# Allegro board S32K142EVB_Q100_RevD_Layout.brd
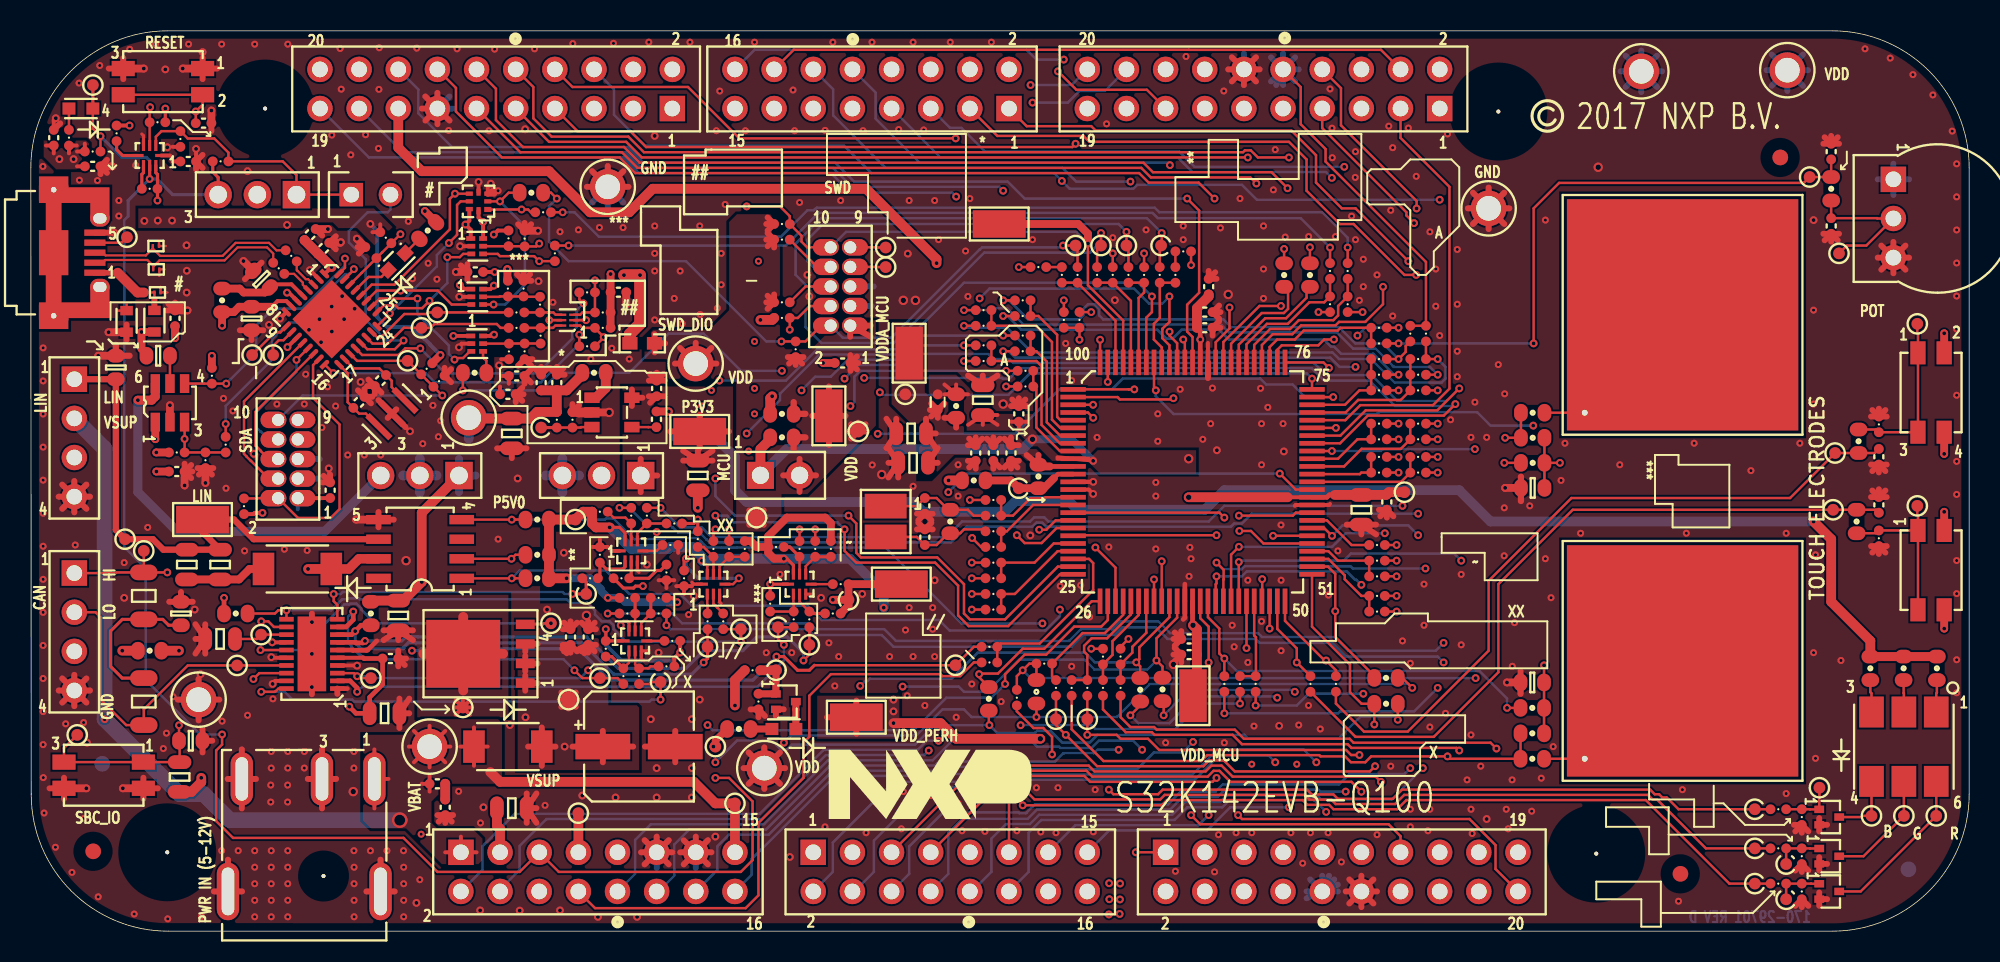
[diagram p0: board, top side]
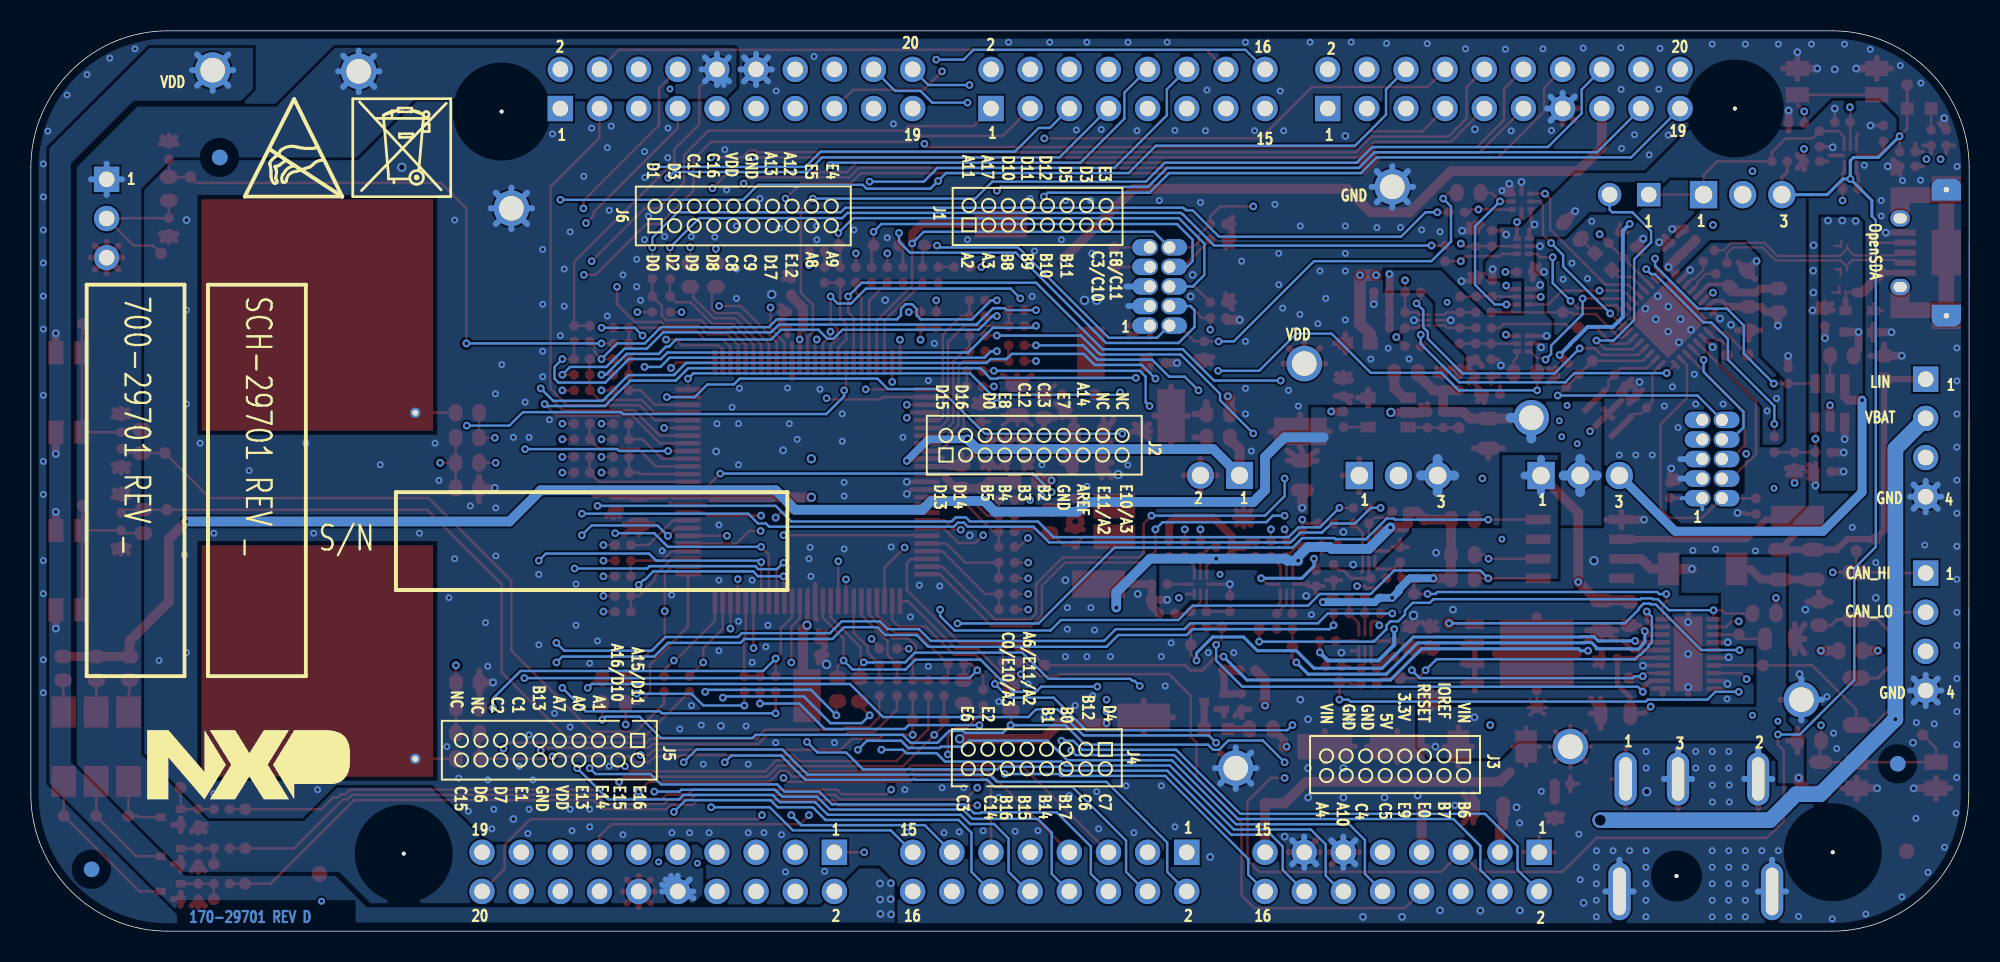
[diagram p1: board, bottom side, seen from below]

Outline 125.76 x 58.42 mm; copper layers: TOP, L2_GND, L3_MIX, BOTTOM. Coordinates in mm from the lower left corner of the outline.
Outline path: 0,49.53 0.03,8.89 0.03,8.89 arc(2.63,2.6) 8.92,0 116.87,0 arc(123.15,2.6) 125.76,8.89 125.76,49.53 arc(123.15,55.82) 116.87,58.42 8.89,58.42 arc(2.6,55.82) 0,49.53

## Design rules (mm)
net group CLOCK: nets SDA_EXTAL SDA_XTAL
net group SDA_USB_CONN_D: nets SDA_USB_CONN_DN SDA_USB_CONN_DP
net group USB_SI_CONN_D: nets SDA_USB_DN SDA_USB_DP
net group POW: nets MIC2005_CSLEW P5V_SDA POWER_EN SDA_RST SDA_USB_P5V_SENSE VTRG_EN
net group POWER_SPACE: nets P5V0_SDA_USB_CONN_VBUS P5V_SDA_PSW SDA_VOUT33
nets with their own width: min track width 0.254; nets GND

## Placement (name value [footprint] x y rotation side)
C1  1000pF  [CC0402_25]  11.21 52.43 0 top
C2  4.7uF  [CC0402_25]  1.49 51.49 90 top
C3  4.7uF  [CC0402_25]  10.21 49.94 0 top
C4  0.1UF  [CC0402_25]  4.01 49.63 0 top
C5  0.1UF  [CC0402_25]  116.8 45.76 270 top
C6  1.0UF  [CC0402_25]  18.12 45.2 45 top
C7  0.1UF  [CC0402_25]  19 44.31 45 top
C8  4.7uF  [CC0402_25]  28.83 42.77 180 top
C9  2.2UF  [CC0603_OV]  14.97 42.31 135 top
C10  0.1UF  [CC0402_25]  38.12 41.46 0 top
C11  10uF  [CC0402_25]  9.35 39.77 90 top
C12  10uF  [CC0603_OV]  14.32 39.75 270 top
C15  18PF  [CC0603_OV]  8.26 37.34 0 top
C16  0.1UF  [CC0402_25]  119.89 30.78 270 top
C17  220PF  [CC0603_OV]  5.51 36.58 90 top
C18  4.7uF  [CC0402_25]  30.95 34.84 0 top
C19  0.1UF  [CC0402_25]  31.52 36.03 0 top
C20  22PF  [CC0402_25]  22.68 35.73 225 top
C21  10.0uF  [CC0805_OV]  31.2 32.3 270 top
C22  0.1uF  [CC0402_25]  34.12 35.6 90 top
C23  22PF  [CC0402_25]  21.29 34.31 45 top
C24  10.0uF  [CC0805_OV]  43.27 29.57 270 top
C25  0.1UF  [CC0402_25]  9.47 29.82 0 top
C26  0.1UF  [CC0402_25]  19.42 28.61 90 top
C27  10.0uF  [CC0805_OV]  22.95 14.14 0 top
C28  0.1UF  [CC0402_25]  119.9 27.66 90 top
C40  4700 PF  [CC0603_OV]  9.74 20.61 90 top
C47  0.1uF  [CC0402_25]  35.01 19.09 90 top
C49  10UF  [CC0805_OV]  31.2 7.98 0 top
C59  0.01UF  [CC0402_25]  40.59 33.21 90 top
C126  12PF  [CC0402_25]  58 27.6 270 top
C127  12PF  [CC0402_25]  58 25.57 90 top
C128  47uF  [CCE6P8X6P8]  39.46 11.98 0 top
C129  0.1uF  [CC0402_25]  76.16 39.15 0 top
C131  0.1uF  [CC0402_25]  75.15 17.95 180 top
C133  0.1uF  [CC0402_25]  76.42 41.82 90 top
C140  0.1uF  [CC0402_25]  64.1 33.57 90 top
C141  0.1uF  [CC0402_25]  75.15 18.96 180 top
C142  0.1uF  [CC0402_25]  76.16 40.17 0 top
C143  10UF  [CC0805_OV]  86.32 27.34 270 top
C144  10UF  [CC0805_OV]  61.76 34.46 90 top
C146  0.1uF  [CC0402_25]  87.97 27.85 270 top
C533  10pF  [CC0603_OV]  97.44 28.76 180 top
C535  10pF  [CC0603_OV]  97.41 16.14 180 top
C536  10.0uF  [CC0805_OV]  12.28 18.96 180 top
C539  10UF  [CC0805_OV]  57.11 32.3 180 top
C540  0.1uF  [CC0402_25]  63.59 31.03 270 top
C541  0.1uF  [CC0402_25]  62.45 31.03 270 top
C542  10UF  [CC0805_OV]  57.24 30.39 180 top
C543  0.1uF  [CC0402_25]  61.3 31.03 270 top
C544  0.1uF  [CC0402_25]  26.38 9.56 0 top
C545  0.1uF  [CC0402_25]  26.89 8.04 270 top
C546  0.1uF  [CC0402_25]  36.16 19.09 90 top
C547  0.1uF  [CC0402_25]  23.33 17.69 0 top
C548  0.1uF  [CC0402_25]  40.6 35.22 90 top
C549  0.1UF  [CC0402_25]  116.8 50.58 90 top
C550  0.1uF  [CC0402_25]  33.11 35.6 90 top
C551  4700 PF  [CC0603_OV]  10.38 12.36 0 top
C552  0.1uF  [CC0402_25]  52.67 36.87 180 top
D1  RED  [LED_0603]  3.25 53.38 0 top
D2  LED GREEN  [LED_0603]  23.73 43.44 225 top
D3  GREEN  [LED_0603]  48.86 13.12 0 top
D6  PMEG3050EP  [SOD-128]  17.29 23.5 180 top
D9  PMEG3050EP  [SOD-128]  30.95 11.98 0 top
D11  LED RED/GRN/BL  [LED6_5X6MM]  121.52 11.97 270 top
D17  PESD5V0R1BSF  [DSN0603-2]  8.22 41.45 180 top
D18  PESD5V0R1BSF  [DSN0603-2]  8.12 44.46 180 top
D19  PESD5V0R1BSF  [DSN0603-2]  8.14 42.94 180 top
GND1  5006  [TP_TH_063]  47.59 10.58 0 top
GND2  5006  [TP_TH_063]  94.58 46.9 0 top
GND3  5006  [TP_TH_063]  10.88 15.02 0 top
GND4  5006  [TP_TH_063]  37.43 48.3 0 top
J1  CON 2X8  [CON2X8_2P54_TH]  63.46 53.38 270 top
J2  CON 2X10  [CON20_2P54_TH]  41.62 53.38 270 top
J3  CON 2X8  [CON2X8_2P54_TH]  27.9 5.12 90 top
J4  CON 2X8  [CON2X8_2P54_TH]  50.76 5.12 90 top
J5  CON 2X10  [CON20_2P54_TH]  73.62 5.12 90 top
J6  CON 2X10  [CON20_2P54_TH]  91.4 53.38 270 top
J7  USB_MICRO_AB  [CON_MICROAB_10F_25_SM_RA]  1.58 44.02 0 top
J10  HDR 1X3  [HDR103_A]  39.57 29.57 270 top
J11  HDR 1X4 RA  [CON_HDR_4M_100_TH_RA]  2.82 35.81 270 top
J12  HDR 2X5  [CON_2RH_10_50]  17.32 28.09 90 top
J13  HDR 1X4 RA  [CON_HDR_4M_100_TH_RA]  2.82 23.24 270 top
J14  HDR 2X5  [CON_2RH_10_50]  53.16 39.29 90 top
J15  HDR1X2  [HDR1X2_5P48X2P69]  47.34 29.58 0 top
J16  CON PWR 3  [CON3_PWR_JACK_TH_PJ051A]  22.29 9.88 90 top
J104  HDR 1X3  [HDR103_A]  17.23 47.79 270 top
J105  HDR 1X2 TH  [SH_HDR102_BOTTOM]  20.79 47.79 90 top
J107  HDR 1X3  [HDR103_A]  27.78 29.57 270 top
L1  330 OHM  [IND_1608]  8.02 39.58 270 top
L2  330 OHM  [IND_1608]  6.21 39.57 270 top
L512  30 OHM  [IND_0402]  58.84 34.33 90 top
NOREF  -  []  110.32 62.4 0 top
NOREF#2  -  []  68.54 2.58 90 top
NOREF#3  -  []  49.17 10.58 0 top
NOREF#4  -  []  50.27 21.87 90 top
NOREF#5  -  []  7.9 41.28 90 top
NOREF#6  -  []  34.42 40 0 top
NOREF#7  -  []  95.76 36.47 270 top
NOREF#8  -  [unnamed#2]  4.05 5.18 0 top
NOREF#9  -  []  49.15 21.89 0 top
NOREF#10  -  []  122.43 32.38 90 top
NOREF#11  -  [unnamed#2]  107.02 3.72 0 top
NOREF#12  -  []  44.06 52.07 90 top
NOREF#13  -  []  8.89 58.42 0 top
NOREF#14  -  []  5.99 55.97 0 top
NOREF#15  -  []  45.68 53.38 0 top
NOREF#16  -  []  38.48 18.21 0 top
NOREF#17  -  []  7.82 42.78 90 top
NOREF#18  -  []  47.3 6.42 90 top
NOREF#19  -  []  7.8 44.62 0 top
NOREF#20  -  []  66.92 52.07 90 top
NOREF#21  -  []  16.58 20.24 0 top
NOREF#22  -  []  39.01 48.3 0 top
NOREF#23  -  []  34.42 39.65 90 top
NOREF#24  -  [unnamed#2]  15.2 53.38 0 top
NOREF#25  -  []  -54.65 -194.91 0 top
NOREF#26  -  []  2.15 10.97 0 top
NOREF#27  -  []  15.09 23.5 0 top
NOREF#28  -  []  13.93 22.9 0 top
NOREF#29  -  []  24.95 7.93 0 top
NOREF#30  -  []  121.48 21.03 90 top
NOREF#31  -  []  11.99 52.07 0 top
NOREF#32  -  []  34.85 38.07 0 top
NOREF#33  -  []  19.88 15.74 90 top
NOREF#34  -  []  39.35 24.03 90 top
NOREF#35  -  []  38.23 24.05 0 top
NOREF#36  -  []  39.6 18.18 90 top
NOREF#37  -  []  7.92 44.46 0 top
NOREF#38  -  []  121.48 25.83 0 top
NOREF#39  -  []  28.95 7.93 90 top
NOREF#40  -  []  115.54 55.87 0 top
NOREF#41  -  []  47.3 6.42 0 top
NOREF#42  -  []  123.57 14.52 90 top
NOREF#43  -  []  96.16 46.9 0 top
NOREF#44  -  []  98.1 6.42 90 top
NOREF#45  -  []  44.48 21.9 90 top
NOREF#46  -  []  70.16 6.42 90 top
NOREF#47  -  []  44.06 52.07 0 top
NOREF#48  -  []  20.03 15.44 90 top
NOREF#49  -  []  0.03 8.89 0 top
NOREF#50  -  []  180.28 58.67 0 top
NOREF#51  -  []  -381.97 187.81 0 top
NOREF#52  -  []  7.13 8.32 90 top
NOREF#53  -  []  28.75 11.98 0 top
NOREF#54  -  []  106.07 55.79 0 top
NOREF#55  -  []  45.68 2.58 90 top
NOREF#56  -  []  43.88 21.87 0 top
NOREF#57  -  []  51.78 7.28 0 top
NOREF#58  -  []  19.29 24.85 90 top
NOREF#59  -  []  45.87 22.75 0 top
NOREF#60  -  []  53.34 39.01 0 top
NOREF#61  -  []  8.85 5.12 0 top
NOREF#62  -  []  121.48 32.55 90 top
NOREF#63  -  []  6.96 50.33 90 top
NOREF#64  -  []  27.46 11.98 0 top
NOREF#65  -  []  -16.59 -34.16 0 top
NOREF#66  -  []  44.68 21.87 90 top
NOREF#67  -  []  7.8 44.29 90 top
NOREF#68  -  []  7.3 9.27 90 top
NOREF#69  -  []  7.82 43.1 0 top
NOREF#70  -  []  116.87 0 0 top
NOREF#71  -  []  47.34 29.58 0 top
NOREF#72  -  []  8.85 5.12 0 top
NOREF#73  -  []  6.98 50.96 0 top
NOREF#74  -  []  7.71 50.98 0 top
NOREF#75  -  []  17.14 52.07 90 top
NOREF#76  -  []  0 49.53 0 top
NOREF#77  -  []  10.97 53.32 90 top
NOREF#78  -  []  70.16 6.42 0 top
NOREF#79  -  []  51.36 7.8 0 top
NOREF#80  -  []  30 33.31 0 top
NOREF#81  -  []  -408 -337.34 0 top
NOREF#82  -  [unnamed#2]  95.21 53.18 0 top
NOREF#83  -  []  122.43 26 0 top
NOREF#84  -  []  2.33 11.92 0 top
NOREF#85  -  []  61.77 52.07 0 top
NOREF#86  -  []  125.76 8.89 90 top
NOREF#87  -  []  78.85 41.27 0 top
NOREF#88  -  []  19.29 27.55 0 top
NOREF#89  -  []  3.1 56.28 0 top
NOREF#90  -  []  122.43 20.85 90 top
NOREF#91  -  []  35.9 38.07 90 top
NOREF#92  -  []  119.42 9.72 90 top
NOREF#93  -  []  8.02 41.45 0 top
NOREF#94  -  []  38.8 18.18 0 top
NOREF#95  -  []  8.85 5.12 0 top
NOREF#96  -  []  39.15 24.06 90 top
NOREF#97  -  []  38.55 24.03 0 top
NOREF#98  -  []  7.94 42.94 0 top
NOREF#99  -  []  50.07 21.9 90 top
NOREF#100  -  []  19.88 15.74 90 top
NOREF#101  -  []  7.91 49.71 90 top
NOREF#102  -  []  12.47 15.02 0 top
NOREF#103  -  []  45.87 22.75 90 top
NOREF#104  -  []  39.4 18.21 90 top
NOREF#105  -  []  11.15 54.27 90 top
NOREF#106  -  [unnamed#2]  101.56 5.03 0 top
NOREF#107  -  []  50.76 5.12 0 top
NOREF#108  -  []  6.17 56.92 0 top
NOREF#109  -  []  27.9 5.12 0 top
NOREF#110  -  []  49.47 21.87 0 top
NOREF#111  -  []  43.56 21.89 0 top
NOREF#112  -  []  116.87 0 90 top
NOREF#113  -  []  122.43 37.53 0 top
NOREF#114  -  []  16.43 21.04 0 top
NOREF#115  -  [unnamed#2]  8.85 5.12 0 top
NOREF#116  -  []  121.52 9.72 0 top
NOREF#117  -  [unnamed#2]  113.5 50.2 0 top
NOREF#118  -  []  44.72 36.83 0 top
NOREF#119  -  []  92.95 6.42 0 top
NOREF#120  -  []  45.68 53.38 90 top
NOREF#121  -  []  7.9 41.61 0 top
NOREF#122  -  []  118.47 14.52 0 top
NOREF#123  -  []  121.48 37.35 0 top
NOREF#124  -  []  54.61 8.05 180 bottom
NOREF#125  -  []  109.82 41.95 270 bottom
NOREF#126  -  []  111.85 47.66 180 bottom
NOREF#127  -  [unnamed#2]  4.63 10.86 180 bottom
NOREF#128  -  [unnamed#2]  113.5 50.2 180 bottom
NOREF#129  -  []  119.34 41.95 270 bottom
NOREF#130  -  []  79.72 19.6 180 bottom
NOREF#131  -  []  105.75 48.3 180 bottom
NOREF#132  -  []  54.66 15.42 180 bottom
NOREF#133  -  []  29.4 21.3 180 bottom
NOREF#134  -  []  118.2 8.55 180 bottom
NOREF#135  -  []  91.82 42.06 180 bottom
NOREF#136  -  [unnamed#2]  121.81 4.01 180 bottom
Q1  PHPT61003PY  [LFPAK5_1P27_5X4]  29.1 18 90 top
Q6  MMBT3904TT1G  [SC_75]  116.67 2.58 270 top
Q7  MMBT3904TT1G  [SC_75]  116.67 4.86 270 top
Q8  MMBT3904TT1G  [SC_75]  116.67 7.4 270 top
Q9  MMBT3904TT1G  [SC_75]  48.98 14.9 270 top
R1  4.7K  [RC0402_25]  5.57 51.77 90 top
R2  330 OHM  [RC0402_25]  2.47 51.49 270 top
R3  10.0K  [RC0402_25]  9.7 51.4 90 top
R4  180K  [RC0402_25]  4.01 50.59 0 top
R5  0  [RC0402_25]  12.31 49.95 180 top
R12  220  [RC0603_OV]  25.75 45.46 225 top
R13  5K  [POT3_3352T]  120.84 48.78 270 top
R14  4.7K  [RC0402_25]  23.03 45 315 top
R15  4.7K  [RC0402_25]  30.99 44.95 270 top
R16  10.0K  [RC0402_25]  32.03 44.94 90 top
R18  0  [RC0402_25]  33.24 46.65 0 top
R20  10.0K  [RC0402_25]  22.06 44.03 135 top
R21  33  [RC0402_25]  16.89 43.82 315 top
R24  0  [RC0402_25]  34 43.98 90 top
R25  33  [RC0402_25]  16.09 43.01 315 top
R30  4.7K  [RC0402_25]  30.95 41.69 270 top
R31  10.0K  [RC0402_25]  31.97 41.69 90 top
R32  0  [RC0402_25]  36.09 41.45 180 top
R35  0  [RC0402_25]  33.04 40.65 90 top
R38  0  [RC0402_25]  31.51 40.15 180 top
R39  10.0K  [RC0402_25]  37.11 40.15 0 top
R41  0  [RC0402_25]  31.51 39.15 180 top
R42  10.0K  [RC0402_25]  37.11 39.15 180 top
R44  10.0K  [RC0402_25]  119.9 32.88 90 top
R47  0  [RC0402_25]  33.07 38.64 270 top
R49  0  [RC0402_25]  36.09 37.95 180 top
R51  10.0K  [RC0402_25]  32.03 37.62 270 top
R52  4.7K  [RC0402_25]  31.02 37.61 90 top
R56  680  [RC0603_OV]  45.94 13.12 0 top
R57  4.7K  [RC0402_25]  25.68 36.49 225 top
R60  10.0K  [RC0402_25]  11.75 36.04 270 top
R62  10.0K  [RC0402_25]  26.48 35.68 45 top
R68  15K  [RC0402_25]  11.33 30.56 270 top
R69  1.0K  [RC0402_25]  12.64 31.57 270 top
R70  10.0K  [RC0402_25]  9.47 31.06 0 top
R74  10.0K  [RC0402_25]  119.9 25.49 270 top
R77  10.0K  [RC0402_25]  13.83 27.57 90 top
R80  2K  [RC0805_OV]  10.12 23.79 270 top
R81  0  [RC0402_25]  62.45 24.93 180 top
R84  0  [RC0402_25]  62.45 25.95 180 top
R88  0  [RC0402_25]  62.45 26.96 180 top
R90  0  [RC0402_25]  62.45 27.98 180 top
R91  1.0M  [RC0603_OV]  59.65 26.58 270 top
R92  60.4  [RC1206_OV]  7.33 21.76 270 top
R95  680  [RC0603_OV]  119.34 17.06 90 top
R96  680  [RC0603_OV]  121.5 17.06 90 top
R97  680  [RC0603_OV]  123.66 17.06 90 top
R98  60.4  [RC1206_OV]  7.33 14.9 270 top
R117  0  [RC0603_OV]  48.73 32.04 180 top
R121  10K  [RC0402_25]  49.62 37.76 90 top
R122  0  [RC0402_25]  67.91 42.58 270 top
R123  0  [RC0402_25]  73.24 42.58 270 top
R124  0  [RC0402_25]  87.46 31.92 180 top
R125  0  [RC0402_25]  90 31.92 180 top
R126  0  [RC0402_25]  87.46 29.76 180 top
R127  0  [RC0402_25]  69.18 42.58 270 top
R128  0  [RC0402_25]  71.21 42.58 270 top
R129  0  [RC0402_25]  90 30.77 180 top
R130  0  [RC0402_25]  68.54 15.79 90 top
R131  0  [RC0402_25]  66.51 15.79 90 top
R132  0  [RC0603_OV]  65.24 15.53 90 top
R133  0  [RC0603_OV]  87.92 16.43 180 top
R134  0  [RC0603_OV]  87.92 14.76 180 top
R135  0  [RC0603_OV]  62.15 15.08 90 top
R136  0  [RC0402_25]  61.81 38.01 180 top
R137  0  [RC0402_25]  64.53 36.36 180 top
R146  0  [RC0402_25]  77.43 16.04 270 top
R147  0  [RC0402_25]  87.34 25.06 0 top
R152  0  [RC0402_25]  84.67 16.04 90 top
R153  0  [RC0402_25]  83.02 16.04 90 top
R154  0  [RC0402_25]  62.45 20.87 180 top
R155  0  [RC0402_25]  62.45 22.9 180 top
R156  0  [RC0402_25]  68.03 39.66 90 top
R161  0  [RC0402_25]  84.29 42.84 270 top
R162  0  [RC0402_25]  85.43 42.84 270 top
R164  0  [RC0402_25]  79.46 16.04 90 top
R165  0  [RC0603_OV]  82.99 42.57 90 top
R166  0  [RC0603_OV]  73.42 15.69 270 top
R167  0  [RC0603_OV]  81.31 42.57 90 top
R168  0  [RC0603_OV]  71.97 15.67 270 top
R169  0  [RC0402_25]  34.12 33.19 270 top
R170  0  [RC0402_25]  35.14 33.19 270 top
R171  2K  [RC0805_OV]  12.28 23.79 270 top
R172  0  [RC0603_OV]  97.44 33.64 180 top
R300  0  [RC0603_OV]  60.03 34.07 270 top
R525  4.7K  [RC0603_OV]  97.44 32.01 180 top
R527  0  [RC0603_OV]  97.41 11.19 180 top
R528  4.7K  [RC0603_OV]  97.41 12.84 180 top
R529  0  [RC0402_25]  62.19 18.45 180 top
R530  4.7K  [RC0603_OV]  32.85 24.42 180 top
R532  0  [RC0402_25]  64.35 38.65 180 top
R533  0  [RC0603_OV]  97.44 30.39 0 top
R534  0  [RC0603_OV]  97.41 14.49 0 top
R535  2.2  [RC0805_OV]  23.84 20.49 270 top
R536  4.7K  [RC0603_OV]  13.3 20.61 0 top
R537  10k  [RC0805_OV]  9.65 10 90 top
R538  4.7K  [RC0603_OV]  32.85 22.9 180 top
R539  0  [RC0402_25]  90 37.12 0 top
R540  0  [RC0402_25]  87.46 37.12 0 top
R541  0  [RC0402_25]  90 36.11 180 top
R542  0  [RC0402_25]  87.46 36.11 180 top
R543  0  [RC0402_25]  61.81 40.3 0 top
R544  0  [RC0402_25]  64.35 39.92 0 top
R545  0  [RC0402_25]  74.76 44.11 0 top
R546  0  [RC0402_25]  65.37 43.09 180 top
R562  4.7K  [RC0402_25]  42.38 22.9 90 top
R567  0  [RC0402_25]  61.81 39.28 180 top
R568  0  [RC0402_25]  64.35 40.93 180 top
R569  0  [RC0603_OV]  61.18 29.25 180 top
R570  4.7K  [RC0603_OV]  32.85 26.71 180 top
R571  4.7K  [RC0402_25]  52.54 22.52 180 top
R572  4.7K  [RC0402_25]  41.49 25.06 180 top
R573  10K  [RC0402_25]  48.73 40.81 0 top
R574  10K  [RC0402_25]  48.73 45.89 0 top
R575  10K  [RC0402_25]  48.73 39.79 180 top
R576  4.7K  [RC0402_25]  41.62 18.83 180 top
R577  0  [RC0402_25]  43.9 20.1 90 top
R578  0  [RC0402_25]  44.92 20.1 90 top
R579  0  [RC0402_25]  49.49 20.23 90 top
R580  0  [RC0402_25]  50.51 20.23 90 top
R581  0  [RC0402_25]  36.28 22.9 0 top
R582  0  [RC0402_25]  38.32 22.9 0 top
R583  0  [RC0402_25]  38.44 16.55 90 top
R584  0  [RC0402_25]  39.46 16.55 90 top
R585  0  [RC0402_25]  44.28 24.8 90 top
R586  0  [RC0402_25]  45.3 24.8 90 top
R587  0  [RC0402_25]  49.87 24.8 90 top
R588  0  [RC0402_25]  50.89 24.8 90 top
R589  0  [RC0402_25]  38.95 26.96 90 top
R590  0  [RC0402_25]  39.97 26.96 90 top
R591  0  [RC0402_25]  38.7 20.61 180 top
R592  0  [RC0402_25]  40.73 20.61 0 top
R593  0  [RC0603_OV]  48.73 33.57 180 top
R594  4.7K  [RC0603_OV]  22.06 20.61 270 top
R595  1K  [RC0603_OV]  118.45 26.58 90 top
R596  1K  [RC0603_OV]  118.58 31.79 270 top
R597  1K  [RC0603_OV]  116.8 48.17 90 top
R598  10K  [RC0402_25]  113.37 3.09 0 top
R599  33K  [RC0402_25]  114.9 2.58 270 top
R600  33K  [RC0402_25]  114.9 4.86 270 top
R601  10K  [RC0402_25]  113.37 5.37 0 top
R602  33K  [RC0402_25]  114.9 7.4 270 top
R603  10K  [RC0402_25]  113.37 7.91 0 top
R604  10K  [RC0402_25]  46.82 16.93 0 top
R605  33K  [RC0402_25]  47.21 14.9 270 top
R606  0  [RC0603_OV]  7.71 18.2 0 top
R607  10.0K  [RC0402_25]  8.22 52.49 180 top
R608  10.0K  [RC0402_25]  7.71 48.17 180 top
R609  10.0K  [RC0402_25]  46.32 24.8 270 top
R610  10.0K  [RC0402_25]  48.35 24.93 0 top
R611  10.0K  [RC0402_25]  51.9 24.8 270 top
R612  10.0K  [RC0402_25]  41.74 26.45 180 top
R613  10.0K  [RC0402_25]  36.92 27.22 0 top
R614  10.0K  [RC0402_25]  40.73 21.63 180 top
R615  10.0K  [RC0402_25]  38.7 21.63 0 top
R616  10.0K  [RC0402_25]  43.27 25.44 270 top
R617  10.0K  [RC0402_25]  47.97 21.25 270 top
R618  10.0K  [RC0402_25]  52.03 20.61 180 top
R619  10.0K  [RC0402_25]  36.92 24.42 270 top
R620  10.0K  [RC0402_25]  41.24 23.28 90 top
R621  10.0K  [RC0402_25]  37.3 18.33 270 top
R622  10.0K  [RC0402_25]  41.24 17.18 180 top
R623  10K  [RC0402_25]  48.73 44.87 0 top
R624  0  [RC0603_OV]  36.54 36.23 0 top
R625  0  [RC0603_OV]  32.47 47.92 180 top
R626  0  [RC0603_OV]  28.79 36.23 0 top
R627  0  [RC0603_OV]  12.41 40.93 270 top
R628  0  [RC0603_OV]  65.37 29.5 270 top
R629  0  [RC0402_25]  78.45 16.04 90 top
R630  0  [RC0402_25]  84.29 40.68 90 top
R632  0  [RC0402_25]  85.43 40.68 90 top
R633  0  [RC0402_25]  72.22 42.58 270 top
R634  0  [RC0402_25]  70.19 42.58 270 top
R635  0  [RC0402_25]  65.75 17.36 0 top
R636  0  [RC0402_25]  67.53 15.79 90 top
R637  0  [RC0402_25]  87.46 32.93 180 top
R638  0  [RC0402_25]  90 32.93 180 top
R640  0  [RC0402_25]  87.46 30.77 180 top
R642  0  [RC0402_25]  90 29.76 180 top
R643  0  [RC0402_25]  90 35.09 0 top
R644  0  [RC0402_25]  87.46 35.09 0 top
R647  10K  [RC0402_25]  90.51 38.77 270 top
R648  10K  [RC0402_25]  89.5 38.77 270 top
R649  0  [RC0402_25]  70.7 15.79 270 top
R650  0  [RC0402_25]  70.7 17.82 90 top
R651  0  [RC0402_25]  69.56 15.79 270 top
R652  0  [RC0402_25]  69.56 17.82 90 top
R653  0  [RC0402_25]  62.45 21.88 180 top
R655  0  [RC0402_25]  62.45 23.91 180 top
R656  0  [RC0402_25]  67.02 39.66 90 top
R658  0  [RC0402_25]  64.53 35.34 180 top
R659  0  [RC0402_25]  61.81 37 180 top
R660  0  [RC0402_25]  62.19 17.44 180 top
R661  0  [RC0402_25]  64.35 37.63 180 top
R662  0  [RC0402_25]  66.89 42.58 270 top
R663  0  [RC0402_25]  74.26 42.58 270 top
R664  0  [RC0402_25]  63.97 15.15 270 top
R665  0  [RC0402_25]  87.46 38.14 180 top
R666  0  [RC0402_25]  87.46 39.15 180 top
R667  0  [RC0402_25]  87.34 23.03 180 top
R668  0  [RC0402_25]  87.34 20.74 180 top
R669  0  [RC0402_25]  87.34 21.76 180 top
R670  0  [RC0402_25]  87.34 24.04 180 top
SH1  0  [SH0603]  39.66 38.15 0 top
SW2  EVQ-P2402W  [SW4_SPST_4P8X3P6_2P5]  123.28 34.95 90 top
SW3  EVQ-P2402W  [SW4_SPST_4P8X3P6_2P5]  123.28 23.43 90 top
SW5  EVQ-P2402W  [SW4_SPST_4P8X3P6_2P5]  8.57 55.12 0 top
SW7  Electrode  [ELECTRODE_SQ_15MM]  107.16 39.99 90 top
SW8  Electrode  [ELECTRODE_SQ_15MM]  107.16 17.54 90 top
SW9  EVQ-P2402W  [SW4_SPST_4P8X3P6_2P5]  4.73 10.12 0 top
TP4  TEST_POINT  [TP_TH_063]  113.96 55.87 270 top
TP5  -  [TPAD_030]  117.31 43.98 270 top
TP6  -  [TPAD_030]  6.24 45.03 90 top
TP7  -  [TPAD_030]  26.37 40.15 315 top
TP8  -  [TPAD_030]  25.35 39.15 315 top
TP9  TEST_POINT  [TP_TH_063]  43.13 36.83 270 top
TP10  -  [TPAD_030]  14.36 37.39 90 top
TP11  -  [TPAD_030]  15.72 37.39 90 top
TP12  -  [TPAD_030]  24.44 37.01 90 top
TP18  -  [TPAD_030]  6.11 25.43 90 top
TP28  -  [TPAD_030]  119.42 7.48 270 top
TP29  -  [TPAD_030]  121.52 7.48 0 top
TP30  -  [TPAD_030]  123.62 7.48 90 top
TP503  -  [TPAD_030]  13.38 17.24 0 top
TP504  -  [TPAD_030]  7.33 24.68 0 top
TP505  -  [TPAD_030]  46.06 19.6 0 top
TP506  -  [TPAD_030]  43.9 18.45 0 top
TP507  -  [TPAD_030]  45.68 8.29 0 top
TP508  -  [TPAD_030]  34.89 15.02 0 top
TP509  -  [TPAD_030]  44.41 11.98 0 top
TP510  -  [TPAD_030]  35.52 7.66 0 top
TP511  -  [TPAD_030]  53.68 32.42 0 top
TP512  -  [TPAD_030]  50.51 18.58 0 top
TP513  -  [TPAD_030]  48.48 19.72 0 top
TP514  -  [TPAD_030]  36.03 21.88 0 top
TP515  -  [TPAD_030]  22.06 16.42 0 top
TP516  -  [TPAD_030]  36.92 16.42 0 top
TP517  -  [TPAD_030]  40.86 16.17 0 top
TP518  -  [TPAD_030]  3.01 12.74 0 top
TP519  -  [TPAD_030]  68.54 13.75 0 top
TP520  -  [TPAD_030]  66.51 13.75 0 top
TP521  -  [TPAD_030]  59.99 17.26 0 top
TP522  TEST_POINT  [TP_TH_063]  25.87 11.98 0 top
TP523  -  [TPAD_030]  28.03 14.52 0 top
TP524  -  [TPAD_030]  33.74 19.98 0 top
TP525  -  [TPAD_030]  53.05 21.5 0 top
TP526  TEST_POINT  [TP_TH_063]  104.48 55.79 0 top
TP527  TEST_POINT  [TP_TH_063]  28.41 33.31 0 top
TP528  -  [TPAD_030]  115.4 48.93 0 top
TP529  -  [TPAD_030]  116.93 27.34 0 top
TP530  -  [TPAD_030]  117.06 31.03 0 top
TP531  -  [TPAD_030]  122.39 27.6 0 top
TP532  -  [TPAD_030]  122.39 39.41 0 top
TP533  -  [TPAD_030]  89.12 28.49 0 top
TP534  -  [TPAD_030]  56.73 34.84 0 top
TP535  -  [TPAD_030]  67.78 44.49 0 top
TP536  -  [TPAD_030]  69.43 44.49 0 top
TP537  -  [TPAD_030]  73.33 44.49 0 top
TP538  -  [TPAD_030]  71.08 44.49 0 top
TP539  -  [TPAD_030]  4.03 54.9 0 top
TP540  -  [TPAD_030]  33.11 32.68 0 top
TP541  -  [TPAD_030]  35.33 26.71 0 top
TP542  -  [TPAD_030]  55.46 43.09 0 top
TP543  -  [TPAD_030]  55.46 44.36 0 top
TP544  -  [TPAD_030]  14.94 19.24 0 top
TP545  -  [TPAD_030]  64.1 28.74 0 top
TPAD93  -  [TPAD_030]  113.88 2.07 0 top
TPAD94  -  [TPAD_030]  111.85 3.09 0 top
TPAD95  -  [TPAD_030]  111.85 5.37 0 top
TPAD96  -  [TPAD_030]  113.88 4.36 0 top
TPAD97  -  [TPAD_030]  111.85 7.91 0 top
TPAD98  -  [TPAD_030]  116.04 9.31 0 top
TPAD99  -  [TPAD_030]  47.08 26.84 0 top
TPAD100  -  [TPAD_030]  48.35 16.93 0 top
TS1  TESTLOOP  [TESTPOINT_135_070MIL]  51.78 33.44 90 top
TS2  TESTLOOP  [TESTPOINT_135_070MIL]  75.4 15.28 90 top
TS3  TESTLOOP  [TESTPOINT_135_070MIL]  56.98 37.5 90 top
TS4  TESTLOOP  [TESTPOINT_135_070MIL]  11.14 26.71 0 top
TS5  TESTLOOP  [TESTPOINT_135_070MIL]  43.4 32.42 0 top
TS6  TESTLOOP  [TESTPOINT_135_070MIL]  53.56 13.88 180 top
TS7  TESTLOOP  [TESTPOINT_135_070MIL]  62.83 45.89 0 top
TS8  TESTLOOP  [TESTPOINT_135_070MIL]  56.48 22.52 0 top
U1  NTSX2102GU8H  [XQFN8_1P45X1P25MM]  7.71 50.33 180 top
U2  74LVC2T45GM,125  [QFN8_1P6X1P6MM]  29.05 47.35 180 top
U4  74LVCH1T45  [UDFN6_1X1P5MM]  28.96 44.44 0 top
U7  74LVCH1T45  [UDFN6_1X1P5MM]  28.96 41.16 0 top
U8  MK20DX128VFM5  [QFN32_S142EP]  19.52 39.71 315 top
U9  74LVC2G14GF,132  [SOT891_6P_0P35_1P05X1P05]  34.83 39.65 180 top
U10  74LVCH1T45  [UDFN6_1X1P5MM]  28.96 38.12 0 top
U11  MIC2005-0.8YM6  [SOT23-6_A]  9.03 34.28 90 top
U15  SPX3819M5-L-3-3  [SOT23_5S]  37.7 33.66 270 top
U19  UJA1169TK/F  [SON20_0P5_3P6X5P6]  18.23 17.99 90 top
U21  TJA1027T/20  [SO8_1P27_4X5]  25.26 24.8 180 top
U26  NTSX2102GU8H  [XQFN8_1P45X1P25MM]  38.95 24.68 0 top
U32  NTSX2102GU8H  [XQFN8_1P45X1P25MM]  44.28 22.52 0 top
U33  NTSX2102GU8H  [XQFN8_1P45X1P25MM]  49.87 22.52 0 top
U34  NTSX2102GU8H  [XQFN8_1P45X1P25MM]  39.2 18.83 0 top
U35  PS32K142  [LQFP100_0P5_14X14]  75.37 29.16 0 top
Y1  8.00MHZ  [XTAL3_3P35X1P45_SM]  23.43 33.58 45 top
Y3  8MHZ  [XTAL2_3P3X2P6]  55.46 26.58 270 top

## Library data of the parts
C1 C6 C9 C11 C16 C17 C20-C24 C27 C28 C40 C47 C49 C126 C127 C129 C131 C133 C140-C144 C146 C536 C539-C548 C550-C552 = CAP_NP
C2-C5 C7 C8 C10 C12 C18 C19 C25 C26 C533 C535 C549 = CAP_NP: tolerance: 10%
C15 = CAP_NP: tolerance: 5%
C59 = CAP_NP: tolerance: 20%
C128 = CAP_POL
D1-D3 = LED
D6 D9 = DIODE_SCHTKY
D11 = LED_TRI_COLOR
D17-D19 = DIODE_BIDIR
GND1-GND4 = TEST_POINT_3
J1 J3 J4 = HDR_2X8_M
J2 J5 J6 = CONN_HDR_10X2
J7 = MICRO_USB_CONN_10PIN
J10 J104 J107 = CONN_HDR_3X1
J11 J13 = CONN_HDR_4X1
J12 J14 = CONN_HDR_5X2: User Part Number: 210-07961-00
J15 J105 = CONN_HDR_2X1
J16 = DC_POWER_JACK_SHD
L1 L2 = BEAD
L512 = INDUCTOR_FERRITE
Q1 = PMOS_5P
Q6-Q9 = NPN
R1 R14 R15 R30 R44 R52 R57 R60 R68-R70 R74 R562 R571 R572 R576 = RES: tolerance: 1%
R2 R4 R12 R20 R21 R25 R32 R35 R38 R41 R47 R49 R56 R62 R77 R80 R81 R84 R88 R90-R92 R95-R98 R117 R121-R137 R146 R147 R152-R156 R161 R162 R164-R172 R300 R525 R527-R530 R532-R546 R567-R570 R573-R575 R577-R606 R623-R630 R632-R638 R640 R642-R644 R647-R653 R655 R656 R658-R670 = RES
R3 R5 R16 R18 R24 R31 R39 R42 R51 R607-R622 = RES: tolerance: 5%
R13 = POT: tolerance: 20%
SH1 = RES_SHORT-2
SW2 SW3 SW5 SW9 = EDGE_MOUNT_PB_SW_2
SW7 SW8 = ELECTRODE
TP4 TP9 TP522 TP526 TP527 = TEST_POINT_0
TP5-TP8 TP10-TP12 TP18 TP28-TP30 TP503-TP521 TP523-TP525 TP528-TP545 TPAD93-TPAD100 = TestLoop
TS1-TS8 = TEST_POINT_4
U1 = NTSX2102GU8H_8P
U2 = 74LVC2T45GM_8P
U4 U7 U10 = 74LVCH1T45_6P
U8 = PK20DX128V_QFN_32P
U9 = NC7WP14
U11 = MIC2005-0.8YM6
U15 = SPX3819M5_FIX_0
U19 = UJA1169TKF_3
U21 = TJA1027T_8P
U26 U32-U34 = NTSX2102GU8H_0
U35 = PS32K142_LQFP_1
Y1 = XTAL_CS
Y3 = XTAL_CS10

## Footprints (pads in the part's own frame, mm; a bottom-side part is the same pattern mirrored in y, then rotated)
CC0402_25
  round 0.635 smd: 1(-0.508,0) 2(0.508,0)
CC0603_OV
  oval 0.889x1.143 smd: 1(-0.762,0) 2(0.762,0)
CC0805_OV
  oval 0.889x1.524 smd: 1(-0.965,0) 2(0.965,0)
CCE6P8X6P8
  rect 3.556x1.651 smd: 1(-2.35,0) 2(2.35,0)
CON2X8_2P54_TH
  rect 1.651x1.651 hole 1.016: 1(0,0)
  round 1.651 hole 1.016: 2(-2.54,0) 3(0,-2.54) 4(-2.54,-2.54) 5(0,-5.08) 6(-2.54,-5.08) 7(0,-7.62) 8(-2.54,-7.62) 9(0,-10.16) 10(-2.54,-10.16) 11(0,-12.7) 12(-2.54,-12.7) 13(0,-15.24) 14(-2.54,-15.24) 15(0,-17.78) 16(-2.54,-17.78)
CON3_PWR_JACK_TH_PJ051A
  round 0.254 hole 2.54 unplated: (-6.3,3.3)
  oval 3.454x1.448 hole 2.819x0.813: 1(0,0) 2(0,8.6) 3(0,3.4)
  oval 3.734x1.448 hole 3.099x0.813: SH1(-7.3,9.5) SH2(-7.3,-0.4)
CON20_2P54_TH
  rect 1.651x1.651 hole 1.016: 1(0,0)
  round 1.651 hole 1.016: 2(-2.54,0) 3(0,-2.54) 4(-2.54,-2.54) 5(0,-5.08) 6(-2.54,-5.08) 7(0,-7.62) 8(-2.54,-7.62) 9(0,-10.16) 10(-2.54,-10.16) 11(0,-12.7) 12(-2.54,-12.7) 13(0,-15.24) 14(-2.54,-15.24) 15(0,-17.78) 16(-2.54,-17.78) 17(0,-20.32) 18(-2.54,-20.32) 19(0,-22.86) 20(-2.54,-22.86)
CON_2RH_10_50
  oval 1.067x1.676 hole 0.787: 1(0,0) 2(0,1.27) 3(1.27,0) 4(1.27,1.27) 5(2.54,0) 6(2.54,1.27) 7(3.81,0) 8(3.81,1.27) 9(5.08,0) 10(5.08,1.27)
CON_HDR_4M_100_TH_RA
  rect 1.651x1.651 hole 1.016: 1(0,0)
  round 1.651 hole 1.016: 2(2.54,0) 3(5.08,0) 4(7.62,0)
CON_MICROAB_10F_25_SM_RA
  rect 1.372x0.406 smd: 1(2.575,-1.3) 2(2.575,-0.65) 3(2.575,0) 4(2.575,0.65) 5(2.575,1.3)
  oval 1.27x1.067 hole 0.864x0.66: 6(2.9,2.225) 7(2.9,-2.225)
  rect 1.905x2.921 smd: 8(-0.1,0)
  custom 0.356x0.356 hole 1.524x0.838: 9(-0.1,4.09) 10(-0.1,-4.09)
DSN0603-2
  rect 0.152x0.254 smd: 1(-0.2,0) 2(0.2,0)
ELECTRODE_SQ_15MM
  rect 15.011x15.011 hole 0.381: 1(-6.35,6.349)
HDR1X2_5P48X2P69
  rect 1.753x1.753 hole 1.118: 1(0,0)
  round 1.753 hole 1.118: 2(2.54,0)
HDR103_A
  rect 1.778x1.778 hole 1.143: 1(0,0)
  round 1.778 hole 1.143: 2(0,-2.54) 3(0,-5.08)
IND_0402
  round 0.635 smd: 1(-0.508,0) 2(0.508,0)
IND_1608
  rect 0.61x0.813 smd: 1(-0.7,0) 2(0.7,0)
LED6_5X6MM
  rect 2.007x1.6 smd: A1(-2.25,2.1) A2(-2.25,0) A3(-2.25,-2.1) C1(2.25,2.1) C2(2.25,0) C3(2.25,-2.1)
LED_0603
  rect 0.838x0.787 smd: A(-0.775,0) C(0.775,0)
LFPAK5_1P27_5X4
  rect 0.61x1.219 smd: 1(-1.905,-2.975) 2(-0.635,-2.975) 3(0.635,-2.975) 4(1.905,-2.975)
  rect 4.394x4.801 smd: 5(0,1.05)
LQFP100_0P5_14X14
  rect 1.651x0.305 smd: 1(-7.75,6) 2(-7.75,5.5) 3(-7.75,5) 4(-7.75,4.5) 5(-7.75,4) 6(-7.75,3.5) 7(-7.75,3) 8(-7.75,2.5) 9(-7.75,2) 10(-7.75,1.5) 11(-7.75,1) 12(-7.75,0.5) 13(-7.75,0) 14(-7.75,-0.5) 15(-7.75,-1) 16(-7.75,-1.5) 17(-7.75,-2) 18(-7.75,-2.5) 19(-7.75,-3) 20(-7.75,-3.5) 21(-7.75,-4) 22(-7.75,-4.5) 23(-7.75,-5) 24(-7.75,-5.5) 25(-7.75,-6) 51(7.75,-6) 52(7.75,-5.5) 53(7.75,-5) 54(7.75,-4.5) 55(7.75,-4) 56(7.75,-3.5) 57(7.75,-3) 58(7.75,-2.5) 59(7.75,-2) 60(7.75,-1.5) 61(7.75,-1) 62(7.75,-0.5) 63(7.75,0) 64(7.75,0.5) 65(7.75,1) 66(7.75,1.5) 67(7.75,2) 68(7.75,2.5) 69(7.75,3) 70(7.75,3.5) 71(7.75,4) 72(7.75,4.5) 73(7.75,5) 74(7.75,5.5) 75(7.75,6)
  rect 0.305x1.651 smd: 26(-6,-7.75) 27(-5.5,-7.75) 28(-5,-7.75) 29(-4.5,-7.75) 30(-4,-7.75) 31(-3.5,-7.75) 32(-3,-7.75) 33(-2.5,-7.75) 34(-2,-7.75) 35(-1.5,-7.75) 36(-1,-7.75) 37(-0.5,-7.75) 38(0,-7.75) 39(0.5,-7.75) 40(1,-7.75) 41(1.5,-7.75) 42(2,-7.75) 43(2.5,-7.75) 44(3,-7.75) 45(3.5,-7.75) 46(4,-7.75) 47(4.5,-7.75) 48(5,-7.75) 49(5.5,-7.75) 50(6,-7.75) 76(6,7.75) 77(5.5,7.75) 78(5,7.75) 79(4.5,7.75) 80(4,7.75) 81(3.5,7.75) 82(3,7.75) 83(2.5,7.75) 84(2,7.75) 85(1.5,7.75) 86(1,7.75) 87(0.5,7.75) 88(0,7.75) 89(-0.5,7.75) 90(-1,7.75) 91(-1.5,7.75) 92(-2,7.75) 93(-2.5,7.75) 94(-3,7.75) 95(-3.5,7.75) 96(-4,7.75) 97(-4.5,7.75) 98(-5,7.75) 99(-5.5,7.75) 100(-6,7.75)
POT3_3352T
  rect 1.651x1.651 hole 1.016: 1(0,0)
  round 1.651 hole 1.016: 2(2.54,0) 3(5.08,0)
QFN8_1P6X1P6MM
  rect 0.457x0.33 smd: 1(-0.6,0.525)
  rect 0.457x0.279 smd: 2(-0.6,0) 3(-0.6,-0.5) 5(0.6,-0.5) 6(0.6,0) 7(0.6,0.5)
  rect 0.279x0.457 smd: 4(0,-0.6) 8(0,0.6)
QFN32_S142EP
  custom 0.07x0.07 smd: 1(-2.4,1.751) 2(-2.4,1.251) 3(-2.4,0.751) 4(-2.4,0.25) 5(-2.4,-0.25) 6(-2.4,-0.751) 7(-2.4,-1.251) 8(-2.4,-1.751) 9(-1.751,-2.4) 10(-1.251,-2.4) 11(-0.751,-2.4) 12(-0.25,-2.4) 13(0.25,-2.4) 14(0.751,-2.4) 15(1.251,-2.4) 16(1.751,-2.4) 17(2.4,-1.751) 18(2.4,-1.251) 19(2.4,-0.751) 20(2.4,-0.25) 21(2.4,0.25) 22(2.4,0.751) 23(2.4,1.251) 24(2.4,1.751) 25(1.751,2.4) 26(1.251,2.4) 27(0.751,2.4) 28(0.25,2.4) 29(-0.25,2.4) 30(-0.751,2.4) 31(-1.251,2.4) 32(-1.751,2.4)
  rect 3.607x3.607 smd: 33(0,0)
RC0402_25
  round 0.635 smd: 1(-0.508,0) 2(0.508,0)
RC0603_OV
  oval 0.889x1.143 smd: 1(-0.762,0) 2(0.762,0)
RC0805_OV
  oval 0.889x1.524 smd: 1(-0.965,0) 2(0.965,0)
RC1206_OV
  oval 1.016x1.778 smd: 1(-1.524,0) 2(1.524,0)
SC_75
  rect 0.483x0.635 smd: 1(-0.5,-0.647) 2(0.5,-0.647) 3(0,0.647)
SH0603
  rect 0.991x0.813 smd: 1(-0.8,0) 2(0.8,0)
SH_HDR102_BOTTOM
  rect 1.524x1.524 hole 1.016: 1(0,0)
  round 1.524 hole 1.016: 2(0,-2.54)
SO8_1P27_4X5
  rect 1.6x0.61 smd: 1(-2.7,1.905) 2(-2.7,0.635) 3(-2.7,-0.635) 4(-2.7,-1.905) 5(2.7,-1.905) 6(2.7,-0.635) 7(2.7,0.635) 8(2.7,1.905)
SOD-128
  rect 1.397x2.108 smd: A(-2.2,0) C(2.2,0)
SON20_0P5_3P6X5P6
  rect 0.305x0.94 smd: 1(-2.25,-1.65) 2(-1.75,-1.65) 3(-1.25,-1.65) 4(-0.75,-1.65) 5(-0.25,-1.65) 6(0.25,-1.65) 7(0.75,-1.65) 8(1.25,-1.65) 9(1.75,-1.65) 10(2.25,-1.65) 11(2.25,1.65) 12(1.75,1.65) 13(1.25,1.65) 14(0.75,1.65) 15(0.25,1.65) 16(-0.25,1.65) 17(-0.75,1.65) 18(-1.25,1.65) 19(-1.75,1.65) 20(-2.25,1.65)
  rect 4.851x1.854 smd: 21(0,0)
SOT23-6_A
  rect 1.219x0.61 smd: 1(-1.25,0.95) 2(-1.25,0) 3(-1.25,-0.95) 4(1.25,-0.95) 5(1.25,0) 6(1.25,0.95)
SOT23_5S
  rect 0.686x0.991 smd: 1(-0.953,-1.295) 2(0,-1.295) 3(0.953,-1.295) 4(0.953,1.295) 5(-0.953,1.295)
SOT891_6P_0P35_1P05X1P05
  rect 0.635x0.152 smd: 1(-0.412,0.35) 2(-0.412,0) 3(-0.412,-0.35) 4(0.412,-0.35) 5(0.412,0) 6(0.412,0.35)
SW4_SPST_4P8X3P6_2P5
  rect 1.499x0.991 smd: 1(2.575,0.85) 2(2.575,-0.85) 3(-2.575,0.85) 4(-2.575,-0.85)
TESTPOINT_135_070MIL
  rect 3.429x1.778 smd: 1(0,0)
TP_TH_063
  round 2.311 hole 1.6: 1(0,0)
TPAD_030
  round 0.762 smd: 1(0,0)
UDFN6_1X1P5MM
  rect 0.584x0.305 smd: 1(-0.418,0.5)
  rect 0.508x0.305 smd: 2(-0.38,0) 3(-0.38,-0.5) 4(0.38,-0.5) 5(0.38,0) 6(0.38,0.5)
unnamed#2
  round 1.016 smd: (0,0)
XQFN8_1P45X1P25MM
  rect 0.787x0.203 smd: 1(-0.75,0)
  rect 0.203x0.711 smd: 2(-0.4,-0.65) 3(0,-0.65) 4(0.4,-0.65) 6(0.4,0.65) 7(0,0.65) 8(-0.4,0.65)
  rect 0.711x0.203 smd: 5(0.75,0)
XTAL2_3P3X2P6
  rect 1.6x2.718 smd: 1(-1,0) 2(1,0)
XTAL3_3P35X1P45_SM
  rect 0.406x2.108 smd: 1(1.2,0) 2(0,0) 3(-1.2,0)

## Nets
GND: C1.2 C2.2 C3.2 C4.2 C5.2 C6.2 C7.2 C8.2 C9.2 C10.2 C11.2 C12.2 C16.2 C17.2 C18.2 C19.2 C20.2 C21.2 C22.2 C23.2 C24.2 C25.2 C26.2 C27.2 C28.2 C40.2 C47.2 C49.2 C59.2 C126.2 C127.2 C128.2 C129.2 C131.2 C133.2 C140.2 C141.2 C142.2 C143.2 C144.2 C146.2 C533.2 C535.2 C536.2 C539.2 C540.2 C541.2 C542.2 C543.2 C545.2 C546.2 C547.2 C548.2 C549.2 C550.2 C551.2 C552.2 D17.1(C1) D18.1(C1) D19.1(C1) GND1.1 GND2.1 GND3.1 GND4.1 J2.13 J3.11 J3.13 J5.12 J6.12 J7.5(GND) J11.4 J12.3(A2) J12.5(A3) J13.4 J14.3(A2) J14.5(A3) J16.2 J16.3 J16.SH1(SHIELD1) J16.SH2(SHIELD2) L2.2 Q6.2(EMITTER) Q7.2(EMITTER) Q8.2(EMITTER) Q9.2(EMITTER) R13.3(B) R16.2 R20.2 R31.2 R44.2 R51.2 R62.2 R68.2 R74.2 R170.1 R575.2 R599.2 R600.2 R602.2 R605.2 SW5.1 SW5.3 SW9.2 SW9.4 U1.4(GND) U2.3(DIR) U2.4(GND) U4.2(GND) U7.2(GND) U8.2(VSS1) U8.8(VSSA) U8.33(EPAD) U9.2(GND) U10.2(GND) U11.2(GND) U15.2(GND) U19.1(GND1) U19.4(GND2) U19.16(GND3) U19.19(GND4) U19.21(EP) U21.5(GND) U26.4(GND) U32.4(GND) U33.4(GND) U34.4(GND) U35.13(VREFL) U35.14(VSS1) U35.37(VSS2) U35.60(VSS3) U35.86(VSS4) Y1.2
P3V3: C24.1 C548.1 J3.7 J10.1 TP510.1(PIN1) TS5.1 U15.5(VOUT)
P3V3_SDA: C3.1 C6.1 C7.1 C10.1 C12.1 C18.1 C19.1 C26.1 J12.1(A1) R1.2 R3.1 R12.1 R15.1 R30.1 R39.2 R42.1 R52.1 R60.1 R77.1 R607.1 R627.2 U1.1(VCCA) U2.7(VCCA) U4.1(VCCA) U7.1(VCCA) U8.1(VDD1) U8.7(VDDA) U8.11(VBAT) U9.5(VCC) U10.1(VCCA)
P5V0: C21.1 C22.1 C550.1 J3.9 J10.3 J107.2 R56.1 R95.2 R96.2 R97.2 R169.1 R624.1 TP509.1(PIN1) TP527.1
P5V0_SDA_USB_CONN_VBUS: D17.2(C2) J7.1(VBUS) L1.1
P5V_SBC: C27.1 C547.1 J107.1 R535.1 R536.1 R562.1 R571.1 R572.1 R576.1 R594.1 R617.1 R618.1 R619.1 R620.1 R621.1 R622.1 TP525.1(PIN1) TS8.1 U19.5(V1) U26.1(VCCA) U32.1(VCCA) U33.1(VCCA) U34.1(VCCA)
P5V_SDA: C11.1 C15.1 C25.1 L1.2 R14.1 R57.1 R70.1 U8.6(VREGIN) U11.1(VIN)
P5V_SDA_PSW: J107.3 U11.6(VOUT)
VBATT: C544.1 D9.A J3.1 J3.15 J11.2 J16.1 R606.2 TP507.1(PIN1) TP522.1
VDD: C552.1 J10.2 J14.1(A1) J15.2 R117.1 R121.1 R573.1 R574.1 R593.1 R604.1 R623.1 SH1.2 SW2.2 SW2.4 SW3.2 SW3.4 TP4.1 TP9.1 TP511.1(PIN1) TPAD99.1(PIN1) TS1.1
VDD_MCU: C129.1 C131.1 C133.1 C140.1 C141.1 C142.1 C143.1 C144.1 C146.1 J15.1 L512.2 R117.2 R300.1 TP533.1(PIN1) TS2.1 U35.10(VDD1) U35.38(VDD2) U35.61(VDD3) U35.87(VDD4)
VDD_PERH: C49.1 J3.3 J5.10 J6.10 R13.1(A) R530.1 R538.1 R570.1 R593.2 R609.1 R610.1 R611.1 R612.1 R613.1 R614.1 R615.1 R616.1 R647.1 R648.1 TP526.1 TP541.1(PIN1) TS6.1 U26.8(VCCB) U32.8(VCCB) U33.8(VCCB) U34.8(VCCB)
VDDA: C539.1 C540.1 C541.1 C542.1 C543.1 L512.1 R300.2 R628.1 TP534.1(PIN1) TS3.1 U35.11(VDDA)
ADC_POT: C549.1 R164.1 R597.2 R665.1 TP528.1(PIN1)
AREF: J2.15 R569.2
BTN0: C16.1 R152.1 R596.2 TP530.1(PIN1)
BTN1: C28.1 R153.1 R595.2 TP529.1(PIN1)
CAN_HI: J13.1 R92.1 TP504.1(PIN1) U19.18(CANH)
CAN_LO: J13.2 R98.2 TP503.1(PIN1) U19.17(CANL)
JTAG_TCLK/SWD_CLK: J14.4(B2) R127.1 R575.1 R626.1 TP536.1(PIN1)
JTAG_TDI: J14.8(B4) R128.1 R623.2 TP538.1(PIN1)
JTAG_TDO: J14.6(B3) R123.1 R573.2 TP537.1(PIN1)
JTAG_TMS/SWD_DIO_PTA4: J14.2(B1) R121.2 R122.1 R625.1 TP535.1(PIN1)
LEDRGB_BLUE: D11.C3(CATHODE3) Q8.3(COLLECTOR) TP28.1(PIN1)
LEDRGB_GREEN: D11.C2(CATHODE2) Q7.3(COLLECTOR) TP29.1(PIN1)
LEDRGB_RED: D11.C1(CATHODE1) Q6.3(COLLECTOR) TP30.1(PIN1)
LIN: C17.1 J11.1 R80.1 R171.1 TP18.1(PIN1) TS4.1 U21.6(LIN)
LIN_RX: R130.1 R538.2 R650.2 R667.1 TP519.1(PIN1) U21.1(RXD)
LIN_SLP: R529.2 R530.2 TP521.1(PIN1) U21.2(S\L\P\)
LIN_TX: R131.1 R570.2 R652.2 R668.1 TP520.1(PIN1) U21.4(TXD)
LVLRST_EN: R1.1 U1.5(OE)
MIC2005_CSLEW: C15.2 U11.5(CSLEW)
POWER_EN: R69.1 U8.31(ADC0_SE7B/PTD6/SPI0_PCS3/UART0_)
PTA0: J5.7 U35.79(PTA0/FTM2_CH1/LPI2C0_SCLS/FXIO_)
PTA1: J5.5 R666.1
PTA2: R540.1 R542.2 R644.1 U35.73(PTA2/FTM3_CH0/LPI2C0_SDA/EWM_OU)
PTA3: R539.1 R541.2 R643.1 U35.72(PTA3/FTM3_CH1/LPI2C0_SCL/EWM_IN)
PTA4: R546.1 R662.1
PTA6: R147.1 U35.58(PTA6/FTM0_FLT1/LPSPI1_PCS1/LPUA)
PTA7: J5.9 U35.57(PTA7/FTM0_FLT2/RTC_CLKIN/LPUART)
PTA8: J6.17 U35.100(PTA8/FXIO_D6/FTM3_FLT3)
PTA9: J6.19 U35.99(PTA9/FXIO_D7/FTM3_FLT2/FTM1_FLT)
PTA10: R545.1 R663.1
PTA11: J1.2 U35.91(PTA11/FTM1_CH5/FXIO_D1/CMP0_RRT)
PTA12: J6.16 U35.90(PTA12/FTM1_CH6/CAN1_RX/FTM2_QD_)
PTA13: J6.14 U35.89(PTA13/FTM1_CH7/CAN1_TX/FTM2_QD_)
PTA14: J2.16 U35.88(PTA14/FTM0_FLT0/FTM3_FLT1/EWM_I)
PTA15: R167.1 U35.83(PTA15/FTM1_CH2/LPSPI0_PCS3/ADC1)
PTA16: R165.1 U35.82(PTA16/FTM1_CH3/LPSPI1_PCS2/ADC1)
PTA17: J1.4 U35.62(PTA17/FTM0_CH6/FTM3_FLT0/EWM_OU)
PTB0: J4.5 R670.1
PTB1: J4.7 R669.1
PTB2: J2.11 U35.48(PTB2/FTM1_CH0/LPSPI0_SCK/FTM1_Q)
PTB3: J2.9 U35.47(PTB3/FTM1_CH1/LPSPI0_SIN/FTM1_Q)
PTB4: J2.7 U35.28(PTB4/FTM0_CH4/LPSPI0_SOUT/TRGMU)
PTB5: J2.5 U35.27(PTB5/FTM0_CH5/LPSPI0_PCS1/LPSPI)
PTB6: R81.1 R84.1 U35.16(PTB6/LPI2C0_SDA/XTAL)
PTB6_XTAL: C127.1 R84.2 R91.2 Y3.2
PTB7: R88.1 R90.1 U35.15(PTB7/LPI2C0_SCL/EXTAL)
PTB7_EXTAL: C126.1 R88.2 R91.1 Y3.1
PTB8: J1.5 U35.77(PTB8/FTM3_CH0)
PTB9: J1.7 U35.76(PTB9/FTM3_CH1/LPI2C0_SCLS)
PTB10: J1.9 U35.75(PTB10/FTM3_CH2/LPI2C0_SDAS)
PTB11: J1.11 U35.74(PTB11/FTM3_CH3/LPI2C0_HREQ)
PTB12: J4.3 U35.68(PTB12/FTM0_CH0/FTM3_FLT2/ADC1_S)
PTB13: J5.11 U35.67(PTB13/FTM0_CH1/FTM3_FLT1/ADC1_S)
PTB14: J4.8 R637.1
PTB15: J4.10 R638.1
PTB16: J4.12 R640.1
PTB17: J4.6 R642.1
PTC0: R146.1 R534.1 U35.40(PTC0/FTM0_CH0/FTM1_CH6/ADC0_SE8)
PTC1: J5.13 R172.2 R525.2 U35.39(PTC1/FTM0_CH1/FTM1_CH7/ADC0_SE9)
PTC2: J5.15 R527.2 R528.2 R636.1
PTC3: R132.2 R533.1 R635.1 R664.1
PTC4: J3.12 R634.1
PTC5: J3.10 R633.1
PTC6: J4.4 R630.1
PTC7: J4.2 R632.1
PTC8: J6.9 U35.56(PTC8/LPUART1_RX/FTM1_FLT0/LPUAR)
PTC9: J6.11 U35.55(PTC9/LPUART1_TX/FTM1_FLT1/LPUAR)
PTC10: R133.2 U35.52(PTC10/FTM3_CH4/TRGMUX_IN11)
PTC11: R134.2 U35.51(PTC11/FTM3_CH5/TRGMUX_IN10)
PTC12: J2.10 R152.2 U35.50(PTC12/FTM3_CH6/FTM2_CH6)
PTC13: J2.12 R153.2 U35.49(PTC13/FTM3_CH7/FTM2_CH7)
PTC14: J4.14 R629.1
PTC15: J5.20 U35.45(PTC15/FTM1_CH3/TRGMUX_IN8/ADC0_)
PTC16: J6.8 U35.44(PTC16/FTM1_FLT2/ADC0_SE14)
PTC17: J6.6 U35.43(PTC17/FTM1_FLT3/ADC0_SE15)
PTD0: J2.6 J6.1 R656.2
PTD1: J6.2 U35.3(PTD1/FTM0_CH3/LPSPI1_SIN/FTM2_C)
PTD2: J6.3 U35.71(PTD2/FTM3_CH4/LPSPI1_SOUT/FXIO_)
PTD3: J1.14 J6.4 U35.70(PTD3/FTM3_CH5/LPSPI1_PCS0/FXIO_)
PTD4: J4.1 U35.69(PTD4/FTM0_FLT3/FTM3_FLT3/ADC1_S)
PTD5: J1.12 U35.33(PTD5/FTM2_CH3/LPTMR0_ALT2/FTM2_)
PTD6: J5.18 R649.2
PTD7: J5.16 R651.2
PTD8: J6.7 U35.42(PTD8/FTM2_FLT2/FXIO_D1/FTM1_CH4)
PTD9: J6.5 U35.41(PTD9/FXIO_D0/FTM2_FLT3/FTM1_CH5)
PTD10: J1.6 R166.1 U35.36(PTD10/FTM2_CH0/FTM2_QD_PHB)
PTD11: J1.8 R168.1 U35.35(PTD11/FTM2_CH1/FTM2_QD_PHA)
PTD12: J1.10 U35.34(PTD12/FTM2_CH2)
PTD13: J2.1 U35.25(PTD13/FTM2_CH4/LPUART1_RX/RTC_C)
PTD14: J2.3 U35.24(PTD14/FTM2_CH5/LPUART1_TX/CLKOU)
PTD15: J2.2 R653.2
PTD16: J2.4 R655.2
PTD17: J6.13 U35.20(PTD17/FTM0_FLT2)
PTE0: J3.6 U35.94(PTE0/LPSPI0_SCK/TCLK1/LPSPI1_SO)
PTE1: J5.14 U35.93(PTE1/LPSPI0_SIN/LPI2C0_HREQ/LPS)
PTE2: J4.13 U35.85(PTE2/LPSPI0_SOUT/LPTMR0_ALT3/FT)
PTE3: J1.16 U35.18(PTE3/FTM0_FLT0/FTM2_FLT0/TRGMUX)
PTE4: J6.20 R658.2
PTE5: J6.18 R659.2
PTE6: J4.15 U35.84(PTE6/LPSPI0_PCS2/FTM3_CH7/LPUAR)
PTE7: J2.14 U35.59(PTE7/FTM0_CH7/FTM3_FLT0)
PTE8: J2.8 R135.2 U35.26(PTE8/FTM0_CH6/CMP0_IN3)
PTE9: J3.8 R660.2
PTE10: R543.2 R567.1 U35.6(PTE10/CLKOUT/FTM2_CH4/FXIO_D4/T)
PTE11: R544.2 R568.1 U35.5(PTE11/LPTMR0_ALT1/FTM2_CH5/FXIO)
PTE12: J6.15 U35.19(PTE12/FTM0_FLT3)
PTE13: J5.8 R661.2
PTE14: J5.6 U35.17(PTE14/FTM0_FLT1/FTM2_FLT1)
PTE15: J5.4 U35.2(PTE15/LPUART1_CTS/FTM2_CH6/FXIO)
PTE16: J5.2 U35.1(PTE16/LPUART1_RTS/FTM2_CH7/FXIO)
RGB_BLUE: R156.2 R603.1 TPAD97.1(PIN1)
RGB_GREEN: R155.2 R601.1 TPAD95.1(PIN1)
RGB_RED: R154.2 R598.1 TPAD94.1(PIN1)
RST_TGTMCU_B: D1.C(CATHODE) J3.5 J14.10(B5) J104.3 R4.2 R5.2 R574.2 R585.2 TP539.1(PIN1) TS7.1 U1.7(B1) U35.97(PTA5/TCLK1/RESET_B)
SBC_CAN_RX: R137.2 R588.2
SBC_CAN_RX_LS: R580.1 TP512.1(PIN1) U19.7(RXD)
SBC_CAN_TX: R136.2 R587.2
SBC_CAN_TX_LS: R579.1 TP513.1(PIN1) U19.2(TXD)
SBC_CS: R129.1 R592.2
SBC_CS_LS: R584.1 TP517.1(PIN1) U19.20(S\C\S\)
SBC_LIMP: R532.2 R586.2
SBC_LIMP_LS: R536.2 R578.1 TP505.1(PIN1) U19.11(L\I\M\P\)
SBC_MISO: R125.1 R591.2
SBC_MISO_LS: R583.1 TP516.1(PIN1) U19.9(SDO)
SBC_MOSI: R126.1 R590.2
SBC_MOSI_LS: R582.1 TP515.1(PIN1) U19.3(SDI)
SBC_RST_LS: R577.1 R594.2 TP506.1(PIN1) U19.8(R\S\T\)
SBC_SCK: R124.1 R589.2
SBC_SCK_LS: R581.1 TP514.1(PIN1) U19.10(SCK)
SDA_EXTAL: C23.1 U8.17(EXTAL0/PTA18/FTM0_FLT2/FTM_CLKI) Y1.3
SDA_JTAG_TCLK: J12.4(B2) U8.12(JTAG_TCLK/SWD_CLK/EZP_CLK/TSI0_)
SDA_JTAG_TDI: J12.8(B4) U8.13(JTAG_TDI/EZP_DI/TSI0_CH2/PTA1/U)
SDA_JTAG_TDO: J12.6(B3) U8.14(JTAG_TDO/TRACE_SWO/EZP_DO/TSI0_)
SDA_JTAG_TMS: J12.2(B1) R77.2 U8.15(JTAG_TMS/SWD_DIO/TSI0_CH4/PTA3/)
SDA_LED: D2.C(CATHODE) U8.29(PTD4/SPI0_PCS1/U\A\R\T\0\_\R\T\)
SDA_LED_R: D2.A(ANODE) R12.2
SDA_RST: J12.10(B5) R57.2 R62.1 TP12.1(PIN1) U8.19(R\E\S\E\T\)
SDA_RST_LED: D1.A(ANODE) R2.1
SDA_RST_TGTMCU_B: J105.2 U8.21(ADC0_SE9/TSI0_CH6/PTB1/I2C0_SDA)
SDA_RST_TGTMCU_J_B: J104.1 J105.1 R3.2 R5.1 U1.2(A1)
SDA_RX_EN: R15.2 R16.1 U4.5(DIR)
SDA_SPI0_CS: R38.2 TP7.1(PIN1) U8.23(ADC0_SE4B/CMP1_IN0/TSI0_CH15/PT)
SDA_SPI0_RST_B: R41.2 TP8.1(PIN1) U8.22(ADC0_SE15/TSI0_CH14/PTC1/SPI0_P)
SDA_SPI0_SCK: U8.26(PTC5/SPI0_SCK/LPTMR0_ALT2/I2S0_) U10.3(A)
SDA_SPI0_SIN: U2.5(2A) U8.28(CMP0_IN1/PTC7/SPI0_SIN/USB_SOF_)
SDA_SPI0_SOUT: U7.3(A) U8.27(CMP0_IN0/PTC6/SPI0_SOUT/PDB0_EX)
SDA_SWD_EN: R41.1 R47.1 U9.6(Y1)
SDA_SWD_EN_B: R49.2 U8.16(N\M\I\/E\Z\P\_\C\S\/TSI0_CH5/PT)
SDA_SWD_EN_B_R: R42.2 R49.1 U9.1(A1)
SDA_SWD_EN_R: R47.2 R51.1 R52.2 U10.5(DIR)
SDA_SWD_OE: R35.1 R38.1 U9.4(Y2)
SDA_SWD_OE_B: R32.2 U8.20(ADC0_SE8/TSI0_CH0/PTB0/I2C0_SCL)
SDA_SWD_OE_B_R: R32.1 R39.1 U9.3(A2)
SDA_SWD_OE_R: R30.2 R31.1 R35.2 U7.5(DIR)
SDA_USB_CONN_DN: D19.2(C2) J7.2(D-) R25.1
SDA_USB_CONN_DP: D18.2(C2) J7.3(D+) R21.1
SDA_USB_DN: R25.2 U8.4(USB0_DM)
SDA_USB_DP: R21.2 U8.3(USB0_DP)
SDA_USB_P5V_SENSE: R14.2 R20.1 U8.30(ADC0_SE6B/PTD5/SPI0_PCS2/U\A\R\)
SDA_USBSHIELD: J7.6(SHELL1) J7.7(SHELL2) J7.8(SHELL3) J7.9(SHELL4) J7.10(SHELL5) L2.1
SDA_VOUT33: C9.1 R627.1 U8.5(VOUT33)
SDA_XTAL: C20.1 U8.18(XTAL0/PTA19/FTM1_FLT0/FTM_CLKIN) Y1.1
SW1_RST_B: C1.1 J104.2 SW5.2 SW5.4
SWD_CLK_TGTMCU_BUF: R626.2 U10.4(B)
SWD_DIO_TGTMCU_BUF: R625.2 U2.2(2B) U7.4(B)
TC_EXTAL_TP: TP11.1(PIN1) U8.10(EXTAL32)
TC_SDA_USB_ID_TP: J7.4(ID) TP6.1(PIN1)
TC_XTAL_TP: TP10.1(PIN1) U8.9(XTAL32)
TP_2102_A: R607.2 U1.3(A2)
TP_2102_B: R608.2 U1.6(B2)
UART1_RX_TGTMCU_BUF: R24.1 U4.4(B)
UART1_RX_TGTMCU_R: U4.3(A) U8.25(PTC4/SPI0_PCS0/UART1_TX/FTM0_CH)
UART1_TX_TGTMCU_BUF: R18.1 U2.1(1B)
UART1_TX_TGTMCU_R: U2.6(1A) U8.24(CMP1_IN1/PTC3/SPI0_PCS1/UART1_R)
UART_RX: R24.2 R161.1
UART_TX: R18.2 R162.1
V_TGTMCU: C2.1 C4.1 C8.1 R2.2 R4.1 R608.1 SH1.1 U1.8(VCCB) U2.8(VCCB) U4.6(VCCB) U7.6(VCCB) U10.6(VCCB)
VSUP: C47.1 C128.1 C546.1 D6.A D9.C Q1.1(EMITTER1) Q1.2(EMITTER2) Q1.3(EMITTER3) R537.1 TP508.1(PIN1) U19.14(BAT) U21.7(VBAT)
VTRG_EN: R68.1 R69.2 R70.2 U11.3(ENABLE)
VTRG_FAULT_B: R60.2 U8.32(PTD7/CMT_IRO/UART0_TX/FTM0_CH7/) U11.4(F\A\U\L\T\)
N20187731: D11.A3(ANODE3) R95.1
N20187747: D11.A2(ANODE2) R96.1
N20224636: C5.1 R13.2(WIPER) R597.1 TP5.1(PIN1)
N20296072: R44.1 R596.1 SW2.1 SW2.3 TP532.1(PIN1)
N20296289: R74.1 R595.1 SW3.1 SW3.3 TP531.1(PIN1)
N20296614: D11.A1(ANODE1) R97.1
N20337791: R122.2 R662.2 U35.98(PTA4/CMP0_OUT/EWM_OUT_B/JTAG_TM)
N20337946: J5.3 R165.2 R166.2
N20338052: R123.2 R663.2 U35.92(PTA10/FTM1_CH4/FXIO_D0/JTAG_TDO)
N20338949: J5.1 R167.2 R168.2
N20339030: R124.2 R637.2 U35.66(PTB14/FTM0_CH2/LPSPI1_SCK/ADC1_)
N20339144: R125.2 R638.2 U35.65(PTB15/FTM0_CH3/LPSPI1_SIN/ADC1_)
N20339274: R126.2 R640.2 U35.64(PTB16/FTM0_CH4/LPSPI1_SOUT/ADC1)
N20339954: R128.2 R633.2 U35.95(PTC5/FTM2_CH0/RTC_CLKOUT/FTM2_Q)
N20341657: J1.13 R132.1 R133.1
N20341806: J1.15 R134.1 R135.1
N20342040: J2.19 R539.2 R567.2 R647.2
N20342083: J2.17 R540.2 R568.2 R648.2
N20342455: R136.1 R659.1 U35.8(PTE5/TCLK2/FTM2_QD_PHA/FTM2_CH3)
N20342663: R137.1 R658.1 U35.9(PTE4/FTM2_QD_PHB/FTM2_CH2/CAN0_)
N20344687: J4.11 R146.2 R541.1 R543.1
N20344693: J4.9 R147.2 R542.1 R544.1
N20349379: R161.2 R630.2 U35.81(PTC6/LPUART1_RX/CAN1_RX/FTM3_CH)
N20349445: R162.2 R632.2 U35.80(PTC7/LPUART1_TX/CAN1_TX/FTM3_CH)
N20351631: R164.2 R629.2 U35.46(PTC14/FTM1_CH2/TRGMUX_IN9/ADC0_)
N20408163: R169.2 R170.2 TP540.1(PIN1) U15.3(EN)
N20408770: C59.1 U15.4(BYP)
N20424711: R154.1 R653.1 U35.22(PTD15/FTM0_CH0/LPSPI0_SCK)
N20424784: R155.1 R655.1 U35.21(PTD16/FTM0_CH1/LPSPI0_SIN/CMP0_)
N20424902: R156.1 R656.1 U35.4(PTD0/FTM0_CH2/LPSPI1_SCK/FTM2_C)
N20428524: R129.2 R642.2 U35.63(PTB17/FTM0_CH5/LPSPI1_PCS3)
N20428906: R127.2 R634.2 U35.96(PTC4/FTM1_CH0/RTC_CLKOUT/EWM_IN)
N20447644: J1.1 R644.2
N20447648: J1.3 R643.2
N20483325: J3.2 R81.2
N20483330: J3.4 R90.2
N20483362: J3.14 R545.2
N20483368: J3.16 R546.2
N20484569: J4.16 R664.2
N20487643: C533.1 R525.1 R533.2
N20487701: R527.1 SW8.1
N20487722: C535.1 R528.1 R534.2
N20492371: R529.1 R660.1 U35.23(PTE9/FTM0_CH7)
N20498073: Q1.4(BASE) TP524.1(PIN1) U19.15(VEXCTRL)
N20502236: R532.1 R661.1 U35.7(PTE13/FTM2_FLT0)
N20519466: C536.1 TP544.1(PIN1) U19.13(V2)
N20529258: D6.C R80.2 R171.2
N20532266: Q1.5(COLLECTOR) R535.2 TP523.1(PIN1) U19.6(VEXCC)
N20533540: R172.1 SW7.1
N20537015: C551.1 R537.2 SW9.1 SW9.3 TP518.1(PIN1) U19.12(WAKE)
N20615858: R590.1 R612.2 U26.6(B2)
N20615860: R589.1 R613.2 U26.7(B1)
N20628442: R585.1 R616.2 U32.7(B1)
N20629726: R577.2 U32.2(A1)
N20726302: R578.2 U32.3(A2)
N20726411: R586.1 R609.2 U32.6(B2)
N20727622: R562.2 U32.5(OE)
N20728836: C40.1 R92.2 R98.1
N20751108: R571.2 U33.5(OE)
N20751111: R587.1 R610.2 U33.7(B1)
N20751112: R588.1 R611.2 U33.6(B2)
N20754157: R572.2 U26.5(OE)
N20757133: R591.1 R615.2 U34.7(B1)
N20757185: R592.1 R614.2 U34.6(B2)
N20757257: R576.2 U34.5(OE)
N20757373: R579.2 R617.2 U33.2(A1)
N20757398: R580.2 R618.2 U33.3(A2)
N20757820: R581.2 R619.2 U26.2(A1)
N20757845: R582.2 R620.2 U26.3(A2)
N20758005: R583.2 R621.2 U34.2(A1)
N20758031: R584.2 R622.2 U34.3(A2)
N20759089: D3.A(ANODE) R56.2
N20788275: Q6.1(BASE) R598.2 R599.1 TPAD93.1(PIN1)
N20788431: Q7.1(BASE) R600.1 R601.2 TPAD96.1(PIN1)
N20788562: Q8.1(BASE) R602.1 R603.2 TPAD98.1(PIN1)
N20797138: Q9.1(BASE) R604.2 R605.1 TPAD100.1(PIN1)
N20798434: D3.C(CATHODE) Q9.3(COLLECTOR)
N20799004: J13.3 R606.1
N20829527: R624.2 U15.1(VIN)
N20859178: R131.2 R635.2 U35.29(PTC3/FTM0_CH3/CAN0_TX/LPUART0_T)
N20859231: R130.2 R636.2 U35.30(PTC2/FTM0_CH2/CAN0_RX/LPUART0_R)
N20864354: R649.1 R650.1 U35.32(PTD6/FTM2_FLT2/CMP0_IN7)
N20864532: R651.1 R652.1 U35.31(PTD7/FTM2_FLT3/CMP0_IN6)
N20866143: R665.2 R666.2 U35.78(PTA1/FTM1_CH1/LPI2C0_SDAS/FXIO_)
N20878661: R569.1 R628.2 TP545.1(PIN1) U35.12(VREFH)
N20881189: R667.2 R670.2 U35.54(PTB0/LPUART0_RX/LPSPI0_PCS0/LPT)
N20881219: R668.2 R669.2 U35.53(PTB1/LPUART0_TX/LPSPI0_SOUT/TCL)
N207179701: C544.2 C545.1
N207665286: J14.7(A4) TP542.1(PIN1)
N207665288: J14.9(A5) TP543.1(PIN1)

Pads without a net: J2 18 20; J5 17 19; J11 3; J12 7 9; U21 3 8

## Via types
v1: diameter 0.508, hole 0.254, TOP to BOTTOM, 493 vias
v2: diameter 0.61, hole 0.356, TOP to BOTTOM, 16 vias
v3: diameter 1.016, hole 0.711, TOP to BOTTOM, 1 via
v4: diameter 0.457, hole 0.203, TOP to BOTTOM, 400 vias

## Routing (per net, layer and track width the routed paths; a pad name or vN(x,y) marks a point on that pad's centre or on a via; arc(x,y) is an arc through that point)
GND: length 680.4
  TOP w0.152: 8.86,41.45 D17.1 8.42,41.8 8.41,41.8 ; 8.32,44.79 D18.1 8.76,44.46 ; 8.34,42.53 8.34,42.53 D19.1 8.67,42.94
  TOP w0.178: U9.2 v1(36.02,39.65)
  TOP w0.203: U1.4 7.31,51.62 7.2,51.73 ; U33.4 50.75,21.87 50.76,21.88 ; 40.09,18.2 40.08,18.18 U34.4 39.6,17.67 39.71,17.56 ; U26.4 39.35,23.39 39.46,23.28 ; 44.79,21.25 44.68,21.36 U32.4
  TOP w0.254: v1(1.62,52.75) 1.49,52.62 C2.2 ; U2.3 29.65,48.31 v1(29.84,48.5) ; U19.4 20.99,17.24 21.04,17.18 21.17,17.18 21.17,17.23 v1(21.17,17.23) ; v1(15.6,17.78) 15.64,17.74 U19.16 ; 84.29,27.72 84.22,27.66 U35.60 82.06,27.66 82,27.6 ; v1(27.77,37.88) 27.95,38.12 U10.2 ; U35.14 68.64,28.66 v1(68.92,28.37) ; U19.19 15.85,16.24 15.71,16.1 15.71,16.04 v1(15.69,16.04) ; U8.8 v1(16.16,39.75) ; U7.2 v1(27.8,41.16) ; U8.2 v1(18.1,42.9) ; C26.2 v1(19.33,30.03) ; U35.86 76.37,38.17 ; U2.4 v1(29.05,48.61) ; U4.2 v1(27.85,44.44) ; C3.2 v1(10.72,50.76)
  TOP w0.279: U35.13 v1(68.93,29.16)
  TOP w0.305: U19.1 20.53,15.74 ; 74.87,22.52 U35.37 74.87,20.34 74.76,20.23
  TOP w0.381: 46.24,10.58 GND1.1 ; GND1.1 47.59,9.23 ; GND1.1 46.57,9.56 ; GND1.1 46.57,11.59 ; GND1.1 48.93,10.58 ; GND1.1 47.59,11.93 ; GND1.1 48.6,11.59 ; GND1.1 48.6,9.56 ; C539.2 56.15,33.25 ; C539.2 55.51,33.25 ; C539.2 55.51,31.34 ; 85.54,1.8 J5.12 ; J5.12 87.1,3.36 ; J5.12 85.54,3.36 ; J5.12 87.1,1.8 ; J5.12 87.34,2.58 ; J5.12 85.31,2.58 ; J5.12 86.32,1.56 ; J5.12 86.32,3.59 ; R62.2 26.84,36.55 ; R62.2 27.26,35.62 ; R62.2 27.26,36.47 ; R44.2 119.9,33.9 ; R44.2 120.32,33.81 ; R44.2 119.47,33.81 ; R44.2 119.39,33.39 ; R44.2 120.4,33.39 ; 14.97,43.38 C9.2 13.89,42.31 ; R68.2 11.75,29.63 ; R68.2 10.91,29.63 ; R68.2 11.84,30.05 ; R68.2 10.82,30.05 ; C28.2 119.9,28.68 ; C28.2 119.47,28.59 ; C28.2 120.4,28.17 ; C28.2 119.39,28.17 ; C28.2 120.32,28.59 ; SW5.1 12.09,55.97 ; SW5.1 11.15,56.66 ; SW5.1 11.15,55.29 ; 1.81,28.19 J11.4 ; J11.4 3.84,28.19 ; J11.4 2.82,29.21 ; J11.4 2.82,27.18 ; J11.4 2.04,28.98 ; J11.4 3.6,28.98 ; J11.4 2.04,27.41 ; J11.4 3.6,27.41 ; C535.2 96.65,16.9 ; 114.9,3.85 R600.2 ; R600.2 115.32,3.93 ; R600.2 114.47,3.93 ; C19.2 32.45,36.45 ; C19.2 32.03,35.52 ; C19.2 32.45,35.6 ; R16.2 32.03,45.96 ; R16.2 31.61,45.87 ; R16.2 32.46,45.87 ; U21.5 23.55,26.7 ; U21.5 22.56,26.21 ; U21.5 22.56,27.2 ; 48.84,14.4 Q9.2 48.34,13.96 ; 8.85,40.28 C11.2 ; C11.2 9.35,40.79 ; C11.2 9.78,40.7 ; C11.2 8.93,40.7 ; 74.13,18.96 C141.2 ; C141.2 74.21,19.38 ; C141.2 74.64,19.47 ; C141.2 74.21,18.54 ; 22.55,34.46 Y1.2 ; Y1.2 23.71,33.86 ; Y1.2 23.15,33.3 ; Y1.2 24.31,32.7 ; 114.39,6.9 R602.2 ; R602.2 114.9,6.39 ; R602.2 114.47,6.47 ; R602.2 115.32,6.47 ; 120.84,42.69 R13.3 ; R13.3 119.82,43.7 ; R13.3 121.85,43.7 ; R13.3 120.84,44.72 ; R13.3 121.62,42.92 ; R13.3 120.06,44.49 ; R13.3 120.06,42.92 ; R13.3 121.62,44.49 ; 42.13,5.12 J3.13 ; J3.13 43.92,4.34 ; J3.13 42.36,4.34 ; J3.13 42.36,5.9 ; J3.13 44.16,5.12 ; J3.13 43.92,5.9 ; J3.13 43.14,6.13 ; C146.2 88.4,26.92 ; C146.2 87.46,27.34 ; C146.2 87.55,26.92 ; C146.2 87.97,26.83 ; 33.7,36.53 C22.2 ; C22.2 34.12,36.61 ; C22.2 34.55,36.53 ; C22.2 34.63,36.11 ; 10.88,13.68 GND3.1 ; GND3.1 9.54,15.02 ; GND3.1 10.88,16.37 ; GND3.1 12.23,15.02 ; 56.27,29.44 C542.2 ; C542.2 55.64,31.34 ; C542.2 55.64,29.44 ; C542.2 55.64,30.39 ; 8.98,21.37 C40.2 ; C40.2 10.5,21.37 ; C40.2 9.74,22.01 ; R605.2 47.63,13.97 ; R605.2 46.7,14.39 ; R605.2 47.21,13.88 ; 60.79,30.52 C543.2 ; C543.2 60.88,30.09 ; C543.2 61.3,30.01 ; C144.2 61.76,36.06 ; C144.2 60.81,36.06 ; C144.2 62.71,36.06 ; 39.82,5.9 J3.11 ; J3.11 41.62,5.12 ; J3.11 41.38,4.34 ; J3.11 40.6,6.13 ; J3.11 39.59,5.12 ; J3.11 39.82,4.34 ; J3.11 41.38,5.9 ; J2.13 27.16,52.6 ; J2.13 26.38,52.36 ; J2.13 25.36,53.38 ; J2.13 25.6,54.16 ; J2.13 25.6,52.6 ; J2.13 26.38,54.39 ; C143.2 87.27,26.38 ; C143.2 85.37,26.38 ; C143.2 87.27,25.74 ; C143.2 86.32,25.74 ; 76.67,38.65 C129.2 ; C129.2 77.18,39.15 ; C129.2 77.09,39.58 ; Q6.2 116.03,2.51 ; Q6.2 116.03,1.65 ; Q6.2 116.54,2.08 ; 31.61,36.69 R51.2 ; R51.2 32.46,36.69 ; R51.2 32.54,37.11 ; SW9.4 2.15,9.96 ; SW9.4 2.15,8.58 ; SW9.4 1.21,9.27 ; C140.2 64.61,34.07 ; C140.2 64.52,34.5 ; C140.2 63.67,34.5 ; C140.2 63.59,34.07 ; C140.2 64.1,34.58 ; 19,29.54 C26.2 ; C26.2 18.91,29.12 ; C26.2 19.42,29.63 ; Q7.2 116.54,4.36 ; Q7.2 116.03,4.8 ; Q7.2 116.03,3.93 ; C23.2 22.07,34.25 ; C23.2 21.22,35.1 ; C23.2 22.15,34.67 ; C23.2 21.64,35.18 ; 119.39,24.99 R74.2 ; R74.2 119.9,24.48 ; R74.2 119.47,24.56 ; R74.2 120.4,24.99 ; R74.2 120.32,24.56 ; 57.58,26.67 C126.2 ; C126.2 57.49,27.09 ; C126.2 58.51,27.09 ; C126.2 58.42,26.67 ; 21.28,43.96 R20.2 21.19,44.39 ; 94.58,45.55 GND2.1 ; GND2.1 95.92,46.9 ; GND2.1 94.58,48.25 ; GND2.1 93.23,46.9 ; GND2.1 95.59,45.89 ; GND2.1 93.56,45.89 ; GND2.1 93.56,47.92 ; GND2.1 95.59,47.92 ; C547.2 24.26,17.27 ; C547.2 23.84,17.18 ; C547.2 23.84,18.2 ; C547.2 24.35,17.69 ; 30.07,48.11 U2.3 30.07,47.85 ; 26.46,7.11 C545.2 ; C545.2 27.31,7.11 ; C545.2 26.38,7.53 ; C545.2 27.39,7.53 ; C545.2 26.89,7.02 ; 77.92,55.14 J6.12 ; J6.12 79.48,55.14 ; J6.12 77.92,56.7 ; J6.12 79.72,55.92 ; J6.12 78.7,54.9 ; J6.12 77.69,55.92 ; J6.12 79.48,56.7 ; 7.3,8.58 SW9.2 ; SW9.2 8.24,9.27 ; SW9.2 7.3,9.96 ; 2.82,14.6 J13.4 ; J13.4 1.81,15.62 ; J13.4 2.82,16.63 ; J13.4 3.84,15.62 ; J13.4 2.04,14.83 ; J13.4 3.6,14.83 ; J13.4 2.04,16.4 ; J13.4 3.6,16.4 ; 74.64,17.44 C131.2 ; C131.2 74.13,17.95 ; C131.2 74.21,17.52 ; C131.2 74.21,18.37 ; C127.2 58.51,26.07 ; C127.2 57.49,26.07 ; C127.2 57.58,26.5 ; C127.2 58.42,26.5 ; Q8.2 116.54,6.9 ; Q8.2 116.03,6.47 ; Q8.2 116.03,7.34 ; 32.69,36.53 C550.2 ; C550.2 33.53,36.53 ; C550.2 33.11,36.61 ; 116.38,44.83 C5.2 ; C5.2 117.31,45.25 ; C5.2 117.23,44.83 ; C5.2 116.8,44.74 ; C5.2 116.29,45.25 ; 18.23,15.37 v1(18.23,17.99) 18.23,20.61 ; 5.05,55.97 SW5.3 ; SW5.3 5.99,55.29 ; SW5.3 5.99,56.66 ; 41.81,10.96 C128.2 ; C128.2 39.84,11.98 ; C128.2 41.81,12.99 ; 31.2,30.7 C21.2 ; C21.2 32.16,31.33 ; C21.2 30.25,31.33 ; J16.3 18.89,11.8 ; J16.3 17.97,9.88 ; J16.3 19.8,9.88 ; J16.3 18.89,7.96 ; 11.87,2.58 J16.SH1 ; J16.SH1 13.7,2.58 ; J16.SH1 12.79,4.64 ; J7.5 v1(5.41,45.32) ; C47.2 35.44,20.02 ; C47.2 35.01,20.1 ; C47.2 34.51,19.6 ; C47.2 34.59,20.02 ; 21.81,35.37 C20.2 ; C20.2 22.32,34.86 ; C20.2 21.9,35.79 ; C20.2 22.74,34.95 ; C546.2 36.67,19.6 ; C546.2 36.58,20.02 ; C546.2 36.16,20.1 ; C546.2 35.73,20.02 ; C2.2 1.91,52.42 ; C25.2 9.98,30.33 ; C25.2 10.4,30.25 ; C25.2 10.48,29.82 ; C25.2 10.4,29.4 ; 14.32,38.36 C12.2 ; C12.2 13.56,38.99 ; C12.2 15.08,38.99 ; 6.21,38.37 L2.2 6.21,39.36 ; 19.78,44.24 C7.2 19.78,45.09 ; 116.29,51.09 C549.2 ; C549.2 116.8,51.6 ; C549.2 117.31,51.09 ; C549.2 117.23,51.52 ; C549.2 116.38,51.52 ; C142.2 77.09,40.59 ; C142.2 77.09,39.75 ; C142.2 77.18,40.17 ; C4.2 4.94,49.2 ; C4.2 4.52,49.12 ; C4.2 4.94,50.05 ; 19.88,15.4 U19.1 ; 10.72,49.44 C3.2 ; C3.2 11.14,50.37 ; C3.2 11.14,49.52 ; 35.56,34.12 R170.1 35.14,34.2 ; 40.09,35.73 C548.2 ; C548.2 41.11,35.73 ; C548.2 41.03,36.15 ; C548.2 40.6,36.23 ; C548.2 40.18,36.15 ; 119.39,30.28 C16.2 ; C16.2 120.32,29.85 ; C16.2 119.47,29.85 ; C16.2 120.4,30.28 ; C16.2 119.89,29.77 ; 114.9,1.56 R599.2 ; R599.2 115.32,1.65 ; R599.2 114.47,1.65 ; 62.45,30.01 C541.2 62.87,30.09 ; C27.2 24.55,14.14 ; C27.2 23.91,15.09 ; C27.2 24.55,15.09 ; C27.2 23.91,13.18 ; C49.2 32.8,8.94 ; C49.2 32.8,7.03 ; C49.2 32.17,7.03 ; C49.2 32.8,7.98 ; C49.2 32.17,8.94 ; 11.71,51.92 C1.2 ; C18.2 31.88,34.41 ; C18.2 31.97,34.84 ; C18.2 31.46,34.33 ; C18.2 31.88,35.26 ; GND4.1 38.77,48.3 ; GND4.1 36.08,48.3 ; GND4.1 36.41,49.31 ; GND4.1 38.44,49.31 ; GND4.1 37.43,49.64 ; C8.2 28.33,43.28 ; C8.2 28.33,42.27 ; C8.2 27.9,43.2 ; C551.2 11.77,12.36 ; C551.2 11.14,11.59 ; C551.2 11.14,13.12 ; 63.17,30.09 C540.2 ; C540.2 64.01,30.09 ; C540.2 63.59,30.01 ; C540.2 64.1,30.52 ; C536.2 11.32,19.91 ; C536.2 10.68,18.96 ; C536.2 11.32,18.01 ; C536.2 10.68,19.91 ; C536.2 10.68,18.01 ; 31.54,42.63 R31.2 ; R31.2 32.39,42.63 ; R31.2 32.47,42.2 ; R31.2 31.97,42.71 ; 76.37,35.89 U35.86 ; C133.2 76.42,42.84 ; C133.2 76.92,42.33 ; C133.2 76.84,42.75 ; J16.SH2 22.69,4.64 ; J16.SH2 21.77,2.58 ; J16.SH2 23.6,2.58 ; 13.69,7.96 J16.2 ; J16.2 13.69,11.8 ; J16.2 14.6,9.88 ; J16.2 12.77,9.88 ; C6.2 18.9,45.13
  TOP w0.406: 96.67,29.49 C533.2 96.67,27.91 ; 5.51,38.05 C17.2 6.4,37.34 ; C535.2 96.65,15.41
  TOP w0.508: C1.2 v1(11.71,53.25) ; C10.2 v1(38.63,40.69) ; R16.2 v1(32.9,45.45) ; C59.2 v1(41.39,33.72) ; C17.2 v1(4.37,37.34) ; C7.2 20.08,44.67 v1(20.11,44.7) ; R68.2 v1(11.33,29.08) ; U15.2 v2(37.52,33.66) ; L2.2 v1(5.04,38.87) ; SW9.4 v1(3.6,9.27) ; R20.2 v1(21.15,44.93) ; C8.2 v1(27.58,42.77) ; SW5.3 v1(7.33,55.97) ; C6.2 v1(19.27,45.56) ; C535.2 v1(95.77,16.14) ; C11.2 v1(10.16,40.28) ; C533.2 v1(95.65,28.76) ; C4.2 v1(5.28,49.63) ; U11.2 v1(9.03,34.12) ; SW5.1 v1(9.86,55.97) ; SW9.2 v1(5.97,9.27) ; C25.2 v1(9.98,28.92) ; 52.16,36.87 v1(51.4,36.87) ; U21.5 v1(21.1,26.7) ; C9.2 v1(13.79,43.48)
  TOP w0.635: U15.2 35.55,33.66 35.52,33.69 R170.1 ; C24.2 v1(43.27,27.47) ; R575.2 48.09,39.66 v1(47.33,39.66)
  L2_GND w0.381: 1.81,28.19 J11.4 ; J11.4 2.82,27.18 ; J11.4 3.6,27.41 ; J11.4 2.04,28.98 ; J11.4 2.82,29.21 ; J11.4 3.6,28.98 ; J11.4 2.04,27.41 ; J11.4 3.84,28.19 ; 85.54,3.36 J5.12 ; J5.12 85.54,1.8 ; J5.12 85.31,2.58 ; J5.12 86.32,3.59 ; J5.12 86.32,1.56 ; J5.12 87.1,3.36 ; J5.12 87.1,1.8 ; J5.12 87.34,2.58 ; 93.23,46.9 GND2.1 ; GND2.1 95.92,46.9 ; GND2.1 95.59,45.89 ; GND2.1 94.58,45.55 ; GND2.1 93.56,45.89 ; GND2.1 94.58,48.25 ; GND2.1 95.59,47.92 ; GND2.1 93.56,47.92 ; 25.6,54.16 J2.13 ; J2.13 27.16,54.16 ; J2.13 26.38,54.39 ; J2.13 27.39,53.38 ; J2.13 27.16,52.6 ; J2.13 25.6,52.6 ; J2.13 25.36,53.38 ; J2.13 26.38,52.36 ; J13.4 3.84,15.62 ; J13.4 2.82,16.63 ; J13.4 2.04,16.4 ; J13.4 2.82,14.6 ; J13.4 3.6,16.4 ; J13.4 2.04,14.83 ; J13.4 1.81,15.62 ; J13.4 3.6,14.83 ; GND1.1 48.6,11.59 ; GND1.1 46.24,10.58 ; GND1.1 47.59,11.93 ; GND1.1 46.57,11.59 ; GND1.1 47.59,9.23 ; GND1.1 48.93,10.58 ; GND1.1 46.57,9.56 ; GND1.1 48.6,9.56 ; 42.36,4.34 J3.13 ; J3.13 43.92,5.9 ; J3.13 44.16,5.12 ; J3.13 42.36,5.9 ; J3.13 43.92,4.34 ; J3.13 42.13,5.12 ; J3.13 43.14,6.13 ; J3.13 43.14,4.1 ; J3.11 40.6,6.13 ; J3.11 41.62,5.12 ; J3.11 39.82,4.34 ; J3.11 39.82,5.9 ; J3.11 41.38,4.34 ; J3.11 41.38,5.9 ; J3.11 40.6,4.1 ; J3.11 39.59,5.12 ; 120.84,42.69 R13.3 ; R13.3 120.06,42.92 ; R13.3 121.62,44.49 ; R13.3 119.82,43.7 ; R13.3 120.06,44.49 ; R13.3 120.84,44.72 ; R13.3 121.62,42.92 ; R13.3 121.85,43.7 ; J6.12 79.72,55.92 ; J6.12 79.48,55.14 ; J6.12 77.92,55.14 ; J6.12 78.7,54.9 ; J6.12 79.48,56.7 ; J6.12 77.69,55.92 ; J6.12 78.7,56.93 ; J6.12 77.92,56.7 ; 36.41,47.28 GND4.1 ; GND4.1 37.43,49.64 ; GND4.1 37.43,46.95 ; GND4.1 38.44,47.28 ; GND4.1 36.41,49.31 ; GND4.1 38.44,49.31 ; GND4.1 38.77,48.3 ; GND4.1 36.08,48.3 ; 11.87,2.58 J16.SH1 ; J16.SH1 13.7,2.58 ; J16.SH1 12.79,4.64 ; 13.69,7.96 J16.2 ; J16.2 13.69,11.8 ; J16.2 14.6,9.88 ; J16.2 12.77,9.88 ; GND3.1 12.23,15.02 ; GND3.1 9.54,15.02 ; GND3.1 10.88,16.37 ; GND3.1 10.88,13.68 ; J16.3 18.89,11.8 ; J16.3 17.97,9.88 ; J16.3 18.89,7.96 ; J16.3 19.8,9.88 ; J16.SH2 22.69,4.64 ; J16.SH2 21.77,2.58 ; J16.SH2 23.6,2.58
  L3_MIX w0.381: 12.77,9.88 J16.2 ; J16.2 13.69,7.96 ; J16.2 13.69,11.8 ; J16.2 14.6,9.88 ; 120.06,44.49 R13.3 ; R13.3 120.06,42.92 ; R13.3 121.85,43.7 ; R13.3 121.62,44.49 ; R13.3 121.62,42.92 ; R13.3 120.84,42.69 ; R13.3 120.84,44.72 ; R13.3 119.82,43.7 ; GND1.1 48.6,11.59 ; GND1.1 46.24,10.58 ; GND1.1 46.57,11.59 ; GND1.1 48.93,10.58 ; GND1.1 47.59,9.23 ; GND1.1 46.57,9.56 ; GND1.1 48.6,9.56 ; GND1.1 47.59,11.93 ; J6.12 79.72,55.92 ; J6.12 79.48,55.14 ; J6.12 78.7,54.9 ; J6.12 77.92,56.7 ; J6.12 79.48,56.7 ; J6.12 77.69,55.92 ; J6.12 77.92,55.14 ; J16.3 18.89,11.8 ; J16.3 19.8,9.88 ; J16.3 18.89,7.96 ; J16.3 17.97,9.88 ; 25.6,52.6 J2.13 ; J2.13 26.38,54.39 ; J2.13 25.36,53.38 ; J2.13 27.16,54.16 ; J2.13 25.6,54.16 ; J2.13 26.38,52.36 ; J2.13 27.16,52.6 ; J2.13 27.39,53.38 ; J3.13 43.92,5.9 ; J3.13 43.92,4.34 ; J3.13 44.16,5.12 ; GND2.1 95.59,45.89 ; GND2.1 94.58,45.55 ; GND2.1 95.59,47.92 ; GND2.1 93.56,47.92 ; GND2.1 95.92,46.9 ; GND2.1 93.23,46.9 ; GND2.1 93.56,45.89 ; GND2.1 94.58,48.25 ; GND4.1 38.44,47.28 ; GND4.1 38.77,48.3 ; GND4.1 37.43,49.64 ; GND4.1 36.41,49.31 ; GND4.1 36.08,48.3 ; GND4.1 36.41,47.28 ; GND4.1 38.44,49.31 ; GND4.1 37.43,46.95 ; 85.54,1.8 J5.12 ; J5.12 87.34,2.58 ; J5.12 87.1,1.8 ; J5.12 86.32,1.56 ; J5.12 85.31,2.58 ; J5.12 86.32,3.59 ; J5.12 87.1,3.36 ; J5.12 85.54,3.36 ; GND3.1 10.88,16.37 ; GND3.1 9.54,15.02 ; GND3.1 12.23,15.02 ; GND3.1 10.88,13.68 ; 1.81,28.19 J11.4 ; J11.4 2.82,27.18 ; J11.4 3.6,27.41 ; J11.4 2.04,27.41 ; J11.4 2.82,29.21 ; J11.4 3.6,28.98 ; J11.4 2.04,28.98 ; J11.4 3.84,28.19 ; J13.4 3.84,15.62 ; J13.4 2.04,16.4 ; J13.4 2.82,14.6 ; J13.4 3.6,16.4 ; J13.4 2.82,16.63 ; J13.4 2.04,14.83 ; J13.4 3.6,14.83 ; J13.4 1.81,15.62 ; J16.SH2 22.69,4.64 ; J16.SH2 23.6,2.58 ; J16.SH2 21.77,2.58 ; J16.SH1 12.79,4.64 ; J16.SH1 13.7,2.58 ; J16.SH1 11.87,2.58
  BOTTOM w0.381: 42.36,4.34 J3.13 ; J3.13 43.92,5.9 ; J3.13 43.92,4.34 ; J3.13 43.14,6.13 ; J3.13 43.14,4.1 ; 77.69,55.92 J6.12 ; J6.12 79.48,55.14 ; J6.12 79.48,56.7 ; J6.12 78.7,56.93 ; J6.12 79.72,55.92 ; J6.12 78.7,54.9 ; J6.12 77.92,55.14 ; J6.12 77.92,56.7 ; 2.82,27.18 J11.4 ; J11.4 3.6,28.98 ; J11.4 3.84,28.19 ; J11.4 2.04,27.41 ; J11.4 1.81,28.19 ; J11.4 2.04,28.98 ; J11.4 2.82,29.21 ; J11.4 3.6,27.41 ; J16.2 13.69,11.8 ; J16.2 14.6,9.88 ; J16.2 12.77,9.88 ; 25.6,54.16 J2.13 ; J2.13 26.38,54.39 ; J2.13 27.16,52.6 ; J2.13 27.39,53.38 ; J2.13 27.16,54.16 ; 11.87,2.58 J16.SH1 ; J16.SH1 12.79,4.64 ; J16.SH1 13.7,2.58 ; GND1.1 47.59,11.93 ; GND1.1 47.59,9.23 ; GND1.1 46.57,11.59 ; GND1.1 48.6,9.56 ; GND1.1 46.24,10.58 ; GND1.1 48.93,10.58 ; GND1.1 46.57,9.56 ; GND4.1 38.77,48.3 ; GND4.1 37.43,49.64 ; GND4.1 37.43,46.95 ; GND4.1 38.44,49.31 ; GND4.1 36.08,48.3 ; GND4.1 38.44,47.28 ; GND4.1 36.41,49.31 ; GND4.1 36.41,47.28 ; J12.5 18.75,30.63 ; 93.56,45.89 GND2.1 ; GND2.1 93.56,47.92 ; GND2.1 94.58,45.55 ; GND2.1 94.58,48.25 ; GND2.1 95.92,46.9 ; GND2.1 95.59,45.89 ; GND2.1 95.59,47.92 ; GND2.1 93.23,46.9 ; 2.04,16.4 J13.4 ; J13.4 1.81,15.62 ; J13.4 2.82,14.6 ; J13.4 2.82,16.63 ; J13.4 3.6,14.83 ; J13.4 2.04,14.83 ; J13.4 3.84,15.62 ; J13.4 3.6,16.4 ; J16.SH2 22.69,4.64 ; J16.SH2 23.6,2.58 ; J16.SH2 21.77,2.58 ; GND3.1 10.88,16.37 ; GND3.1 10.88,13.68 ; GND3.1 9.54,15.02 ; J12.3 18.75,29.36 ; J3.11 40.6,6.13 ; J3.11 40.6,4.1 ; J3.11 39.82,5.9 ; J3.11 41.38,5.9 ; J3.11 39.82,4.34 ; J16.3 18.89,11.8 ; J16.3 17.97,9.88 ; J16.3 19.8,9.88 ; 54.69,41.83 J14.5 ; 54.56,40.56 J14.3
  vias: v1(3.64,12.23) v1(6.06,21.63) v1(8.72,55.92) v1(10.1,44.51) v1(10.12,42.85) v1(10.11,41.44) v1(10.63,20.87) v1(11.01,16.68) v1(11.15,57.04) v1(14.06,49.31) v1(14.47,30.98) v1(15.45,39.34) v1(18.05,39.02) v1(18.24,20.05) v1(18.23,15.84) v1(18.73,39.71) v1(18.83,38.21) v1(19.52,40.53) v1(19.53,38.91) v1(20.2,41.2) v1(20.33,39.71) v1(21.01,40.39) v1(21.39,35.64) v1(24.6,32.44) v1(25.02,1.84) v1(29.15,1.35) v1(29.36,8.04) v1(31.08,13.37) v1(31.58,29.38) v1(31.72,1.34) v1(32.07,52.03) v1(32.94,42.18) v1(33.49,20.87) v1(34.33,1.35) v1(35.78,8.8) v1(36.79,0.93) v1(37.93,8.67) v1(39.33,0.93) v1(39.97,23.79) v1(40.22,13.75) v1(40.47,51.6) v1(40.6,10.58) v1(40.6,8.67) v1(40.73,18.07) v1(42.89,13.75) v1(42.89,10.58) v1(42.89,8.67) v1(43.4,15.02) v1(44.41,6.14) v1(49.24,4.81) v1(50.38,42.58) v1(50.51,41.19) v1(51.27,21.63) v1(53.94,21.88) v1(56.9,43.96) v1(58.64,22.77) v1(64.84,25.68) v1(70.33,40.94) v1(76.95,31.2) v1(80.99,13.32) v1(81.29,31.13) v1(94.45,7.28) v1(115.66,46.14) v2(20.92,9.06) v2(24.35,24.04) v2(36.05,20.49) v2(55.21,29.63) v2(56.6,40.93) v2(57.39,40.93) v2(63.08,34.2) v2(74.13,17.31) v2(77.69,41.31) v2(101.69,49.57) v4(0.78,49.62) v4(0.8,37.85) v4(0.8,35.7) v4(0.8,33.56) v4(0.8,31.41) v4(0.8,29.27) v4(0.8,27.12) v4(0.8,24.98) v4(0.8,22.83) v4(0.8,20.69) v4(0.8,18.54) v4(0.8,16.4) v4(0.8,14.25) v4(0.8,12.11) v4(0.81,9.96) v4(0.86,7.67) v4(1.6,5.45) v4(2.26,13.45) v4(2.67,3.82) v4(2.88,25.06) v4(3.13,55.03) v4(3.15,48.73) v4(3.42,13.54) v4(3.46,7.32) v4(4.32,48.71) v4(4.37,2.23) v4(4.47,56.17) v4(5.71,47.41) v4(5.71,46.4) v4(6.06,23.91) v4(6.41,57.22) v4(6.8,49.7) v4(6.71,1.11) v4(7.58,26.2) v4(8.09,57.55) v4(8.6,11.85) v4(8.8,12.85) v4(8.88,0.8) v4(9.23,15.21) v4(10.23,57.55) v4(11.07,0.96) v4(12.38,57.55) v4(12.38,5.22) v4(12.5,34.57) v4(12.41,13.63) v4(12.66,28.74) v4(13.11,33.76) v4(13.45,5.22) v4(13.87,24.68) v4(14.06,14.01) v4(14.52,57.55) v4(14.52,5.22) v4(14.52,4.15) v4(14.52,3.08) v4(14.52,2) v4(14.52,0.93) v4(15.6,11.66) v4(15.6,10.58) v4(15.57,9.48) v4(15.57,8.38) v4(15.6,5.22) v4(15.6,4.15) v4(15.6,3.08) v4(15.6,2) v4(15.6,0.93) v4(15.71,15.07) v4(15.96,34.2) v4(16.45,24.78) v4(16.67,57.55) v4(16.67,11.66) v4(16.67,10.58) v4(16.66,9.48) v4(16.66,8.38) v4(16.67,5.22) v4(16.67,4.15) v4(16.67,3.08) v4(16.67,2) v4(16.67,0.93) v4(17.74,34.2) v4(17.74,11.66) v4(17.74,10.58) v4(17.83,36.14) v4(17.93,24.7) v4(18.88,32.68) v4(19.25,35.32) v4(19.53,51.65) v4(19.77,34.07) v4(20.07,57.27) v4(20.14,54.63) v4(20.56,30.9) v4(20.76,50.37) v4(20.96,11.66) v4(20.96,10.58) v4(20.96,5.22) v4(20.97,4.15) v4(20.97,3.08) v4(20.97,2) v4(20.97,0.93) v4(21.63,30.9) v4(21.72,51.68) v4(22.03,5.22) v4(22.58,54.62) v4(22.55,50.79) v4(22.6,57.32) v4(22.7,30.9) v4(23.11,5.22) v4(24.18,5.22) v4(24.19,4.15) v4(24.19,3.08) v4(24.19,2) v4(24.19,0.93) v4(24.49,46.06) v4(24.76,42.34) v4(25.04,57.3) v4(25.23,3.34) v4(25.32,6.29) v4(25.43,31.63) v4(25.78,43.34) v4(26.09,34.11) v4(26.34,42.3) v4(26.44,32.08) v4(26.59,33.12) v4(27.1,51.95) v4(27.65,57.25) v4(27.75,9.07) v4(29.17,7.02) v4(29.72,51.93) v4(30.09,57.23) v4(30.31,48.04) v4(30.31,25.44) v4(32.68,57.25) v4(33.36,8.17) v4(33.87,40.81) v4(34.33,45.38) v4(35.16,57.59) v4(35.52,45.5) v4(36.33,37.13) v4(36.89,45.66) v4(37.69,37.83) v4(37.8,57.61) v4(38.42,45.65) v4(38.82,37.12) v4(40.09,57.68) v4(40.47,45.76) v4(40.47,43.98) v4(40.47,42.84) v4(40.47,39.66) v4(41.74,41.06) v4(42.13,42.84) v4(42.26,39.42) v4(42.67,20.54) v4(42.76,57.68) v4(43.4,45.76) v4(43.42,40.02) v4(43.52,34.07) v4(44.16,35.09) v4(44.47,51.94) v4(44.54,40.42) v4(44.69,54.51) v4(44.79,43.98) v4(44.79,41.95) v4(45.05,47.16) v4(46.36,51.94) v4(46.57,31.15) v4(46.95,57.68) v4(46.95,38.27) v4(46.95,35.22) v4(46.95,33.57) v4(47.21,43.47) v4(47.71,18.07) v4(48.6,23.15) v4(49.36,18.07) v4(49.45,54.58) v4(49.55,51.94) v4(49.87,47.28) v4(51.53,51.96) v4(51.52,6.77) v4(51.78,18.71) v4(52.03,57.68) v4(52.16,15.91) v4(52.41,17.82) v4(52.41,9.44) v4(52.54,47.41) v4(53.99,51.94) v4(54.19,6.39) v4(54.57,57.68) v4(54.59,30.25) v4(54.7,9.44) v4(55.71,17.82) v4(56.3,52.02) v4(56.48,6.64) v4(56.6,9.06) v4(56.74,19.54) v4(56.86,15.28) v4(56.98,47.41) v4(56.98,20.99) v4(57.24,57.68) v4(57.24,28.87) v4(57.24,17.82) v4(57.93,51.99) v4(58,14.64) v4(58.38,8.8) v4(58.51,20.99) v4(58.51,19.6) v4(58.64,47.41) v4(58.64,17.82) v4(58.89,44.87) v4(59.65,57.68) v4(60.03,13.88) v4(60.16,30.26) v4(60.16,28.23) v4(60.16,8.29) v4(60.41,6.52) v4(60.64,44.13) v4(60.79,41.19) v4(60.92,47.54) v4(61.05,16.04) v4(61.9,6.48) v4(62.32,57.68) v4(62.95,14.9) v4(62.95,8.67) v4(63.97,6.52) v4(64.99,44.87) v4(65.24,9.31) v4(65.52,6.44) v4(66.51,6.39) v4(66.64,9.31) v4(66.78,22.39) v4(67.14,38.14) v4(67.53,35.73) v4(67.53,17.18) v4(68.11,22.45) v4(68.69,20.39) v4(68.93,6.44) v4(69.05,9.18) v4(69.18,32.04) v4(69.79,52.38) v4(69.94,24.93) v4(70.19,45) v4(72.35,45.5) v4(72.99,29.12) v4(72.99,28.23) v4(72.99,24.8) v4(73.11,33.57) v4(73.11,31.79) v4(73.62,12.23) v4(74.26,3.89) v4(74.56,35.16) v4(74.76,45.76) v4(74.76,44.87) v4(74.95,56.76) v4(75.2,24.9) v4(75.15,23.03) v4(75.27,24.17) v4(76.03,31.92) v4(76.54,32.93) v4(76.66,35.24) v4(76.8,3.85) v4(77.05,6.26) v4(77.18,45.63) v4(77.4,54.52) v4(77.43,12.23) v4(77.94,19.85) v4(78.07,18.45) v4(78.19,6.39) v4(78.45,47.54) v4(78.96,22.77) v4(78.96,17.44) v4(79.21,10.83) v4(79.21,6.39) v4(79.35,13.31) v4(79.78,35.22) v4(79.84,32.93) v4(79.84,30.26) v4(79.84,20.1) v4(79.97,45.76) v4(79.97,42.96) v4(79.97,41.06) v4(80.25,33.99) v4(80.61,48.1) v4(80.73,50.71) v4(81.11,26.36) v4(81.11,22.77) v4(81.11,18.2) v4(81.24,32.93) v4(81.38,45.04) v4(81.75,6.39) v4(82.13,10.83) v4(82.26,13.37) v4(82.51,4.41) v4(82.89,14.64) v4(82.9,45.07) v4(83.02,6.39) v4(83.65,13.12) v4(84.18,21.81) v4(84.16,6.39) v4(84.29,54.65) v4(84.42,52.11) v4(84.43,50.19) v4(84.64,45.07) v4(84.8,24.68) v4(85.03,4.49) v4(85.69,46.39) v4(85.94,50.58) v4(85.93,48.91) v4(85.94,44.87) v4(86.19,40.93) v4(86.45,43.6) v4(86.45,41.82) v4(87.34,42.58) v4(87.34,6.26) v4(88.1,52.24) v4(88.23,46.77) v4(88.23,10.71) v4(88.35,50.84) v4(88.35,39.92) v4(88.99,18.83) v4(89.37,52.11) v4(89.5,17.38) v4(89.5,7.91) v4(89.5,6.77) v4(89.88,48.98) v4(90.39,22.52) v4(90.39,19.85) v4(90.64,6.52) v4(90.77,45.38) v4(90.77,13.25) v4(90.77,7.91) v4(91.15,42.96) v4(91.15,40.55) v4(91.4,38.65) v4(91.78,14.14) v4(91.91,51.73) v4(92.11,33.19) v4(92.54,44.23) v4(92.54,40.68) v4(92.54,37.63) v4(92.54,35.98) v4(92.8,23.15) v4(92.8,18.58) v4(93.18,9.82) v4(93.43,32.04) v4(93.43,12.74) v4(93.43,7.91) v4(93.51,6.34) v4(93.69,34.33) v4(94.07,10.71) v4(94.45,32.04) v4(95.21,36.76) v4(95.59,27.47) v4(95.59,24.36) v4(95.62,34.87) v4(95.72,7.91) v4(95.85,6.64) v4(96.1,9.82) v4(96.11,17.19) v4(96.26,20.02) v4(97.24,27.6) v4(97.37,7.79) v4(97.99,9.93) v4(98.26,46.14) v4(98.26,24.17) v4(98.63,21.64) v4(98.77,11.98) v4(99.28,29.25) v4(99.53,31.66) v4(100.55,25.82) v4(103.09,30.26) v4(106.9,1.94) v4(107.15,9.18) v4(107.4,25.82) v4(107.91,31.66) v4(111.59,29.88) v4(113.88,25.82) v4(113.88,8.93) v4(114.77,31.66) v4(115.66,40.3) v4(115.66,34.2) v4(115.66,18.07) v4(115.79,24.42) v4(115.79,11.21) v4(117.44,17.56) v4(119,57.25) v4(120.63,56.65) v4(122.11,55.58) v4(123.4,54.26) v4(124.65,51.91) v4(124.94,49.79) v4(124.94,47.65) v4(124.94,45.5) v4(124.94,43.36) v4(124.94,41.21) v4(124.94,39.07) v4(124.94,34.77) v4(124.94,30.48) v4(124.94,28.34) v4(124.94,24.05) v4(124.94,21.9) v4(124.94,17.61) v4(124.94,15.47)
